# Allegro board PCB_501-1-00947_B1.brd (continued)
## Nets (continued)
VDD_SD3: C110.1 C184.1 C185.1 C186.1 C187.1 C188.1 R45.2 R46.2 R93.1 R94.1 U7.K8 U10.C6 U10.M4 U10.N4 U10.P3 U10.P5
VDD_SD_CON: C195.1 C196.1 FB42.2 J28.4 R103.1 TP83.1
VDD_SNVS_1P8_CAP: C95.1 U7.AE8
VDD_SOC_ARM: C63.1 C64.1 C65.1 C68.1 C69.1 C70.1 C71.1 C72.1 C73.1 C79.1 C80.1 C81.1 C82.1 C83.1 C84.1 C85.1 FB22.2 R718.2 TP79.1 U5.47 U7.C14 U7.C17 U7.C20 U7.D14 U7.D17 U7.D20 U7.F3 U7.F4 U7.F18 U7.F19 U7.F22 U7.F23 U7.J3 U7.J4 U7.J22 U7.J23 U7.M3 U7.M4 U7.P18 U7.R3 U7.R4 U7.R17 U7.T18 U7.U13 U7.U15 U7.U17 U7.V12 U7.V14 U7.V16 U7.V18 U50.11
VDD_SOC_ARM_L1: L3.1 U5.48
VDD_SOC_ARM_SNS: C40.1 C550.1 L3.2 R718.1 U50.12
VDD_SPK: C269.1 C270.1 FB40.2 U24.21 U24.26
VDDA_1P0_CAP: C86.1 C87.1 U7.V3
VDDA_1P8: C90.1 C91.1 C107.1 D34.2 FB2.2 U7.V5 U7.V6 U7.W5
VDDA_ADC_1P8: C130.1 C131.1 C362.1 FB3.2 U7.AB3 U7.AC3 U7.AC4
VDDA_CLKGEN_1V8: C404.1 C405.1 FB4.2 U42.16
VDDA_PHY_1P8: C66.1 C67.1 C78.1 C357.1 U7.J13 U7.Y9 U7.Y10 U7.Y11 U7.Y12
VDDA_PHY_1V8: C280.1 C283.1 C284.1 C285.1 C507.1 C508.1 FB19.1 U13.13 U13.48
VDDA_PHY_2V5: C286.1 C287.1 C288.1 C289.1 C290.1 C291.1 FB20.1 U13.3 U13.9
VDDD_1P0_CAP: C74.1 C75.1 C76.1 C77.1 U7.AA9 U7.AA10 U7.AA11 U7.AA12 U7.J15 U7.J17
VDDIO_PHY_3V3: C249.1 C250.1 C292.1 C293.1 C294.1 C295.1 C296.1 C297.1 FB21.1 R129.1 R301.2 R302.2 R306.2 R663.2 R664.2 R665.2 R688.2 U13.19 U13.30 U13.41
2G4_ANT: C529.2 M1.32
32K_OSC_EN: R705.1 Y5.1
ADDR_LGHTSEN: R674.2 R683.1 U31.2
ALS_I2C_SCL: R242.1 U31.4
ALS_I2C_SDA: R247.1 U31.6
ALS_INT: R658.2 U7.J20 U31.5
AUD_3V3: C271.1 FB41.2 R366.1 U24.32
AUD_I2C_SCL: R515.1 U24.17
AUD_I2C_SDA: R520.1 U24.18
AUDIO_MCLK: R110.2 U24.11
AUDIO_RXD: R485.2 U24.16
AUDIO_RXD_R: R485.1 U7.D16
AUDIO_TXC: R486.2 U24.12
AUDIO_TXC_R: R486.1 U7.D15
AUDIO_TXD: R483.2 U24.14
AUDIO_TXD_R: R483.1 U7.D19
AUDIO_TXFS: R487.2 U24.13
AUDIO_TXFS_R: R487.1 U7.E19
BASE_PNP: Q35.2 Q35.5 Q35.6 R615.1
BAT_CTRL: Q32.3 R613.1 R614.2
BAT_IN: C569.1 J2.1 Q32.4 Q32.8(SOURCE2)
BOOT_MODE0: SW3.4 U7.P4
BOOT_MODE1: SW3.3 U7.P5
BT_CFG4: R204.2 R697.2 SW2.8
BT_CFG5: R203.2 R698.2 SW2.7
BT_CFG6: R206.2 R699.2 SW2.6
BT_CFG10: R210.2 R700.2 SW2.5
BT_CFG11: R209.2 R701.2 SW2.4
BT_CFG12: R211.2 R702.2 SW2.3
BT_CFG13: R213.2 R703.2 SW2.2
BT_CFG14: R212.2 R704.2 SW2.1
BT_DBG: M1.43 TP55.1
BT_REG_ON: M1.41 U7.J6
BUCK_FB: C531.2 R695.1 R696.2 U46.4
BUCK_FB_L: L7.1 U46.2(SW)
BUCK_PG: R692.2 U7.L25 U46.6
CAMERA_I2C_SCL: J20.7 R639.2 U45.4
CAMERA_I2C_SDA: J20.8 R638.2 U45.5
CAMERA_PWDN: J20.13 Q39.2(SOURCE) R636.1
CAN2_RX: U7.T5 U25.4
CAN2_TX: U7.T6 U25.1
CAN_STB: R224.1 R381.1 U25.8
CANH: C282.1 J19.7 P14.2 R245.2 U25.7
CANL: C281.1 J19.2 P13.2 R246.2 U25.6
CAP_2G4_ANT: C529.1 C530.2 L8.1
CAP_IND_2G4_ANT: C530.1 J10.1(SIG)
CC_RES: BH1.1(POS) C557.1 R737.1
CCM_CLK1_N: TP8.1 U7.Y1
CCM_CLK1_P: TP7.1 U7.Y2
CCM_CLK2: R641.1 TP9.1 U7.W3
CLK_32K: R706.1 Y5.3
CLKGEN_OE0_B: R155.1 U42.12
CLKGEN_OE1_B: R449.1 U42.19
CLKGEN_Q0_N: R598.1 U42.14
CLKGEN_Q0_P: R597.1 U42.13
CLKGEN_Q1_N: R633.1 U42.18
CLKGEN_Q1_P: R632.1 U42.17
CLKGEN_XIN: C402.1 U42.1 X4.1
CLKGEN_XOUT: C403.1 U42.2(XTAL_OUT) X4.2
CODEC_GPIO_INT: U7.K24 U24.15
COLL_GPIO3: Q41.3 R752.2 R763.1
COLL_PMIC_LED: D33.1(K) Q40.3
COLLECTOR_PNP: Q34.3 Q35.3 R616.2
CSENS1_I2C_SCL: R723.1 U50.6
CSENS1_I2C_SDA: R724.1 U50.7
CSENS1_PV: R727.1 U7.L23 U50.10
CSENS2_A0: R732.1 U52.5
CSENS2_I2C_SCL: R726.1 U52.6
CSENS2_I2C_SDA: R725.1 U52.7
CSENS2_PV: R731.1 U7.L24 U52.10
CSI_AGND: J20.2 J20.4 R269.1
CSI_I2C_SCL: R516.1 U45.1
CSI_I2C_SDA: R521.1 U45.8
CSI_PIN30: J20.30 R622.1
CSI_PWDN: Q39.3 R637.1 U7.G25
CSI_RESET: C456.1 J20.9 R630.1
CSI_VDD_1V8: C446.1 C447.1 FB36.1 J20.28 R622.2 R630.2
CSI_XCLK: J20.25 Y4.3
CSI_XCLK_OE: R623.2 Y4.1
D_USB_DN: J11.2 P19.2 R160.2
D_USB_DP: J11.3 P18.2 R158.2
DBG_DA: R165.1 U18.2
DBG_RXLED1: D8.2 R161.1
DBG_RXLED2: D10.2 R166.1
DBG_TXLED1: D9.2 R162.1
DBG_TXLED2: D11.2 R167.1
DBG_XTIN: C243.2 R164.1 U18.43 X5.1
DBG_XTOUT: C244.2 R164.2 U18.44(XTOUT) X5.3
DC34_SEL: R37.2 U5.17
DC_SW: R12.1 SW1.1
DC_SW_CTL: C394.2 D20.1(K) Q2.3 R12.2 R539.1
DDR_SDCLK0_N: R618.1 U7.AD25
DDR_SDCLK0_P: R617.1 U7.AD24
DDR_VREF: C141.1 C535.1 U7.AC13 U8.H1 U8.M8 U9.H1 U9.M8 U51.6
DEBUG_5V0: C226.1 C227.1 C228.1 C239.1 C361.1 FB10.2 R157.1 R161.2 R162.2 R165.2 R166.2 R167.2 R294.2 U18.3 U18.4 U18.14 U18.31 U18.42
DEBUG_5V0_USB: FB10.1 J11.1(VBUS) P17.2
DRAM0_ZQ: R83.2 U8.L8(ZQ)
DRAM0_ZQ1: R81.1 U8.L9
DRAM1_ZQ: R84.2 U9.L8(ZQ)
DRAM1_ZQ1: R82.2 U9.L9
DRAM_ADDR0: U7.AB19 U8.N3 U9.N3
DRAM_ADDR1: U7.AB16 U8.P7 U9.P7
DRAM_ADDR2: U7.AC18 U8.P3 U9.P3
DRAM_ADDR3: U7.AC20 U8.N2 U9.N2
DRAM_ADDR4: U7.AB21 U8.P8 U9.P8
DRAM_ADDR5: U7.Y23 U8.P2 U9.P2
DRAM_ADDR6: U7.V22 U8.R8 U9.R8
DRAM_ADDR7: U7.Y22 U8.R2 U9.R2
DRAM_ADDR8: U7.W22 U8.T8 U9.T8
DRAM_ADDR9: U7.V23 U8.R3 U9.R3
DRAM_ADDR10: U7.T23 U8.L7 U9.L7
DRAM_ADDR11: U7.U22 U8.R7 U9.R7
DRAM_ADDR12: U7.T22 U8.N7 U9.N7
DRAM_ADDR13: U7.P23 U8.T3 U9.T3
DRAM_ADDR14: U7.AB18 U8.T7 U9.T7
DRAM_ADDR15: U7.AB20 U8.M7 U9.M7
DRAM_CAS_B: U7.AC14 U8.K3 U9.K3
DRAM_CS0_B: U7.AB23 U8.L2 U9.L2
DRAM_CS1_B: U7.AA22 U8.L1 U9.L1
DRAM_DATA0: U7.AD22 U8.D7
DRAM_DATA1: U7.AD23 U8.C8
DRAM_DATA2: U7.AE20 U8.C3
DRAM_DATA3: U7.AE23 U8.B8
DRAM_DATA4: U7.AE22 U8.A7
DRAM_DATA5: U7.AD19 U8.A3
DRAM_DATA6: TP15.1 TP16.1 U7.AD18 U8.A2
DRAM_DATA7: U7.AE19 U8.C2
DRAM_DATA8: U7.AE14 U8.E3
DRAM_DATA9: U7.AE18 U8.H8
DRAM_DATA10: U7.AE17 U8.F8
DRAM_DATA11: U7.AD16 U8.H7
DRAM_DATA12: U7.AE16 U8.F7
DRAM_DATA13: U7.AD14 U8.H3
DRAM_DATA14: U7.AD13 U8.G2
DRAM_DATA15: U7.AE13 U8.F2
DRAM_DATA16: U7.AA25 U9.D7
DRAM_DATA17: U7.W24 U9.C8
DRAM_DATA18: TP17.1 TP18.1 U7.V25 U9.B8
DRAM_DATA19: U7.W25 U9.A7
DRAM_DATA20: U7.AC25 U9.A2
DRAM_DATA21: U7.AB25 U9.C3
DRAM_DATA22: U7.AB24 U9.A3
DRAM_DATA23: U7.AC24 U9.C2
DRAM_DATA24: U7.R25 U9.E3
DRAM_DATA25: U7.N24 U9.H8
DRAM_DATA26: U7.P25 U9.H7
DRAM_DATA27: U7.N25 U9.F8
DRAM_DATA28: U7.U25 U9.G2
DRAM_DATA29: U7.R24 U9.F7
DRAM_DATA30: U7.U24 U9.H3
DRAM_DATA31: U7.V24 U9.F2
DRAM_DQM0: U7.AD20 U8.D3
DRAM_DQM1: U7.AD17 U8.E7
DRAM_DQM2: U7.AA24 U9.D3
DRAM_DQM3: U7.P24 U9.E7
DRAM_ODT0: U7.AC16 U8.K1 U9.K1
DRAM_ODT1: U7.AA14 U8.J1 U9.J1
DRAM_RAS_B: U7.AB15 U8.J3 U9.J3
DRAM_RESET: R116.1 U7.AC22 U8.T2 U9.T2
DRAM_SDBA0: U7.R22 U8.M2 U9.M2
DRAM_SDBA1: U7.P22 U8.N8 U9.N8
DRAM_SDBA2: U7.N23 U8.M3 U9.M3
DRAM_SDCKE0: R118.1 U7.AB17 U8.K9 U9.K9
DRAM_SDCKE1: R117.1 U7.AB22 U8.J9 U9.J9
DRAM_SDCLK0_N: R90.2 R91.2 R618.2 TP23.1 TP24.1 U8.K7 U9.K7
DRAM_SDCLK0_P: R90.1 R91.1 R617.2 TP21.1 TP22.1 U8.J7 U9.J7
DRAM_SDQS0_N: TP41.1 TP42.1 U7.AD21 U8.B7
DRAM_SDQS0_P: TP40.1 TP43.1 U7.AE21 U8.C7
DRAM_SDQS1_N: U7.AE15 U8.G3
DRAM_SDQS1_P: U7.AD15 U8.F3
DRAM_SDQS2_N: TP44.1 TP46.1 U7.Y25 U9.B7
DRAM_SDQS2_P: TP45.1 TP47.1 U7.Y24 U9.C7
DRAM_SDQS3_N: U7.T25 U9.G3
DRAM_SDQS3_P: U7.T24 U9.F3
DRAM_SDWE_B: U7.AB14 U8.L3 U9.L3
DRAM_ZQ: R86.2 U7.AB13
EEPROM_I2C1_SCL: R233.1 U41.6
EEPROM_I2C1_SDA: R237.1 U41.5
EMI_GPIO3: Q41.2(EMITTER) R764.2
ENET_INT_B: R680.2 R688.1 U7.M1
ENET_MDC: R95.1 U13.16
ENET_MDIO: R129.2 U7.R5 U13.17
ENET_RST_B: R131.2 U7.R2 U13.43
ESPI3_MISO: R358.2 U7.D9 U23.12
ESPI3_MOSI: R357.2 U7.D8 U23.14
ESPI3_SCLK: R356.2 U7.E9 U23.16
FB_HPOUTL: D23.2(K2) FB11.2 J15.2 R367.2
FB_HPOUTR: D24.2(K2) FB12.2 J15.3
FB_VDD_SD: FB42.1 Q6.3 R102.2
FT_RSTOUT_B: R159.2 U18.5
FT_RX1: U17.3 U18.23
FT_RX2: U18.39 U19.3
FT_TX1: U17.2 U18.24
FT_TX2: U18.40 U19.2
FUSE_FSOURCE: C93.1 R30.1 U7.V8
GPANAIO: TP6.1 U7.V4
GPIO1: R762.1 U5.11
GPIO3: R752.1 U5.26
GPIO_EPDC_D4: C366.1 TP10.1 U7.N22
GPIO_SD3_CLK: R444.2 U7.C1
GPIO_SD3_CMD: R445.2 U7.E1
GPIO_SD3_DATA0: R436.2 U7.B2
GPIO_SD3_DATA1: R437.2 U7.A2
GPIO_SD3_DATA2: R439.2 U7.G2
GPIO_SD3_DATA3: R438.2 U7.F1
GPIO_SD3_DATA4: R440.2 U7.F2
GPIO_SD3_DATA5: R441.2 U7.E2
GPIO_SD3_DATA6: R443.2 U7.C2
GPIO_SD3_DATA7: R442.2 U7.B1
GPIO_SD3_RESET_B: R446.2 U7.G1
GPIO_SD3_STROBE: R447.2 U7.J1
GWDOG_RST_B: C382.1 U7.N1
HP_DETEC: J15.4(TIP_SWITCH) R366.2 U24.2
HP_L: C274.1 U24.31
HP_R: C275.1 U24.29
HPOUTL: C274.2(CATHODE) C369.1 FB11.1
HPOUTR: C275.2(CATHODE) C370.1 FB12.1
HSIC_DATA: J4.1(SIG) U7.A12
HSIC_STROBE: J3.1(SIG) U7.B12
I2C1_SCL: R231.1 R232.1 R233.2 R234.1 U7.J2
I2C1_SDA: R235.1 R236.1 R237.2 R238.2 U7.K1
I2C2_SCL: R61.1 R242.2 R506.2 U7.K2
I2C2_SDA: R62.1 R247.2 R504.2 U7.K3
I2C3_SCL: R63.1 R508.2 R723.2 R726.2 U7.K5
I2C3_SDA: R64.1 R509.2 R724.2 R725.2 U7.K6
I2C4_SCL: R33.1 R515.2 R516.2 R595.2 U7.C12
I2C4_SDA: R34.1 R520.2 R521.2 R596.2 U7.D12
INT_LDO: C542.1 U5.35
JT_PWR: C572.1 H2.1 R171.1
JTAG_GND1: H2.7 R567.1
JTAG_GND2: H2.9 R568.1
JTAG_MOD: R174.2 R387.1 U7.U1
JTAG_TCK: H2.4 U7.U5
JTAG_TDI: H2.8 R169.1 U7.U3
JTAG_TDO: H2.6 U7.U6
JTAG_TMS: H2.2 R170.1 U7.U4
JTAG_TRST_B: R172.1 U7.U2
LCD1_CLK: J14.32 R109.1
LCD1_DATA0: J14.1 U7.D21
LCD1_DATA1: J14.2 U7.A22
LCD1_DATA2: J14.3 U7.B22
LCD1_DATA3: J14.4 U7.A23
LCD1_DATA4: J14.5 R204.1 U7.C22
LCD1_DATA5: J14.6 R203.1 U7.B23
LCD1_DATA6: J14.7 R206.1 U7.A24
LCD1_DATA7: J14.8 U7.F20
LCD1_DATA8: J14.10 U7.E21
LCD1_DATA9: J14.11 U7.C23
LCD1_DATA10: J14.12 R210.1 U7.B24
LCD1_DATA11: J14.13 R209.1 U7.G20
LCD1_DATA12: J14.14 R211.1 U7.F21
LCD1_DATA13: J14.15 R213.1 U7.E22
LCD1_DATA14: J14.16 R212.1 U7.D23
LCD1_DATA15: J14.17 U7.C24
LCD1_DATA16: J14.19 U7.B25
LCD1_DATA17: J14.20 U7.G21
LCD1_DATA18: J14.21 U7.E23
LCD1_DATA19: J14.22 U7.D24
LCD1_DATA20: J14.23 U7.C25
LCD1_DATA21: J14.24 U7.E24
LCD1_DATA22: J14.25 U7.D25
LCD1_DATA23: J14.26 U7.G23
LCD1_ENABLE: J14.28 U7.F25
LCD1_HSYNC: J14.29 U7.E25
LCD1_PWM: J14.50 R758.1 U7.N2
LCD1_RESET: J14.49 U7.C21
LCD1_TP_REF: C266.2 U23.9
LCD1_VSYNC: J14.30 U7.F24
LCD_I2C_SCL: J14.42 R508.1
LCD_I2C_SDA: J14.43 R509.1
LCD_PWR_EN: Q38.1 R734.2 U7.G24
LD_WLAN_B: D6.1(K) R146.1
LD_WPAN_B: D7.1(K) R147.1
LD_WWAN_B: D5.2(K) R145.1
LED_BOOT_COMPL: DA1.3 U7.H23
LED_BOOT_PROC: DA1.4(RK) U7.H22
LED_WLAN_B: J8.44 R146.2
LED_WPAN_B: J8.46 R147.2
LED_WWAN_B: J8.42 R145.2
LIN1: C260.1 U24.4
LIN2: C318.1 U24.3
LVLTXR_OE: R640.1 U45.6
MIC_N: MK1.2 R678.2 R679.1 R684.2
MIC_P: C318.2 MK1.1(POS) R182.2
MICBIAS: C272.1 R182.1 U24.1
MIPI_CSI_CLK_N: J20.20 U7.A15
MIPI_CSI_CLK_P: J20.19 U7.B15
MIPI_CSI_D0_N: J20.23 U7.A16
MIPI_CSI_D0_P: J20.22 U7.B16
MIPI_CSI_D1_N: J20.17 U7.A14
MIPI_CSI_D1_P: J20.16 U7.B14
MIPI_VREG_0P4V: C92.1 U7.H18
MX7_ONOFF: C367.1 R249.1 SW6.3 SW6.4 U7.AC8
MX7_RST_B: C368.1 D21.1(K) R347.1
NVCC_DRAM_CKE: C140.1 R85.1 U7.Y20
OTG1_CHD_B: TP48.1 U7.C7
OTG1_REXT: R66.2 U7.A7
OTG2_REXT: R70.2 U7.A11
OTG_VBUS: C298.1 FB18.2 Q24.3 R570.2 R571.1
OTG_VBUS_CTRL: Q24.1 Q25.3 R570.1
OUT3: C276.1 U24.30
OVRPRTC: Q5.1 R6.1 R8.2
OVRPRTC_LED: D2.1(K) Q5.3
OVRPRTC_LED_PWR: D2.2 R4.2
PCIE_CLK_GEN_SCL: R595.1 U42.8
PCIE_CLK_GEN_SDA: R596.1 U42.9
PCIE_CLKGEN_SS_SEL: R604.1 U42.23
PCIE_CTXM: C207.2 J8.31
PCIE_CTXP: C208.2 J8.33
PCIE_DIS_B: J8.20(W_DISABLE#) U7.T2
PCIE_REFCLK_N: R607.2 R608.1 R633.2 U7.AE10
PCIE_REFCLK_P: R605.2 R606.1 R632.2 U7.AD10
PCIE_REFCLKOUT_N: R598.2 R645.1 U7.AC10
PCIE_REFCLKOUT_N0: J8.11 R634.2 R645.2
PCIE_REFCLKOUT_P: R597.2 R644.1 U7.AB10
PCIE_REFCLKOUT_P0: J8.13 R635.2 R644.2
PCIE_REXT: R80.2 U7.AA13
PCIE_RST_B: J8.22 U7.T3
PCIE_RX_N: R96.1 U7.AE11
PCIE_RX_P: R97.1 U7.AD11
PCIE_RXN_R: J8.23 R96.2
PCIE_RXP_R: J8.25 R97.2
PCIE_SMB_CLK: J8.30 R506.1
PCIE_SMB_DATA: J8.32 R504.1
PCIE_TX_N: C207.1 U7.AC11
PCIE_TX_P: C208.1 U7.AB11
PCIE_UIM_CLK: J7.C3 J8.12
PCIE_UIM_DATA: J7.C7 J8.10
PCIE_UIM_PWR: C571.1 J7.C1 J8.8
PCIE_UIM_RST: J7.C2 J8.14
PCIE_UIM_VPP: J7.C6(VPP) J8.16
PCIE_USB_DM: FL3.4 J8.36
PCIE_USB_DP: FL3.1 J8.38
PHY_CLKOUT: TP62.1 U13.18
PHY_CT: C576.1 J27.1
PHY_GPIO0: R664.1 R666.2 U13.39
PHY_GPIO1: R665.1 R667.2 U13.40
PHY_INT_B: R680.1 U13.44
PHY_JTAG: R741.1 U13.20 U13.22 U13.23
PHY_LED0: D14.2 R663.1 R668.2 U13.47
PHY_LED1: J27.13 R301.1 R307.2 U13.46
PHY_LED2: J27.12 R302.1 R308.2 U13.45
PHY_MDI_A_M: J27.3 U13.2 U53.2 U53.9
PHY_MDI_A_P: J27.2 U13.1 U53.1 U53.10(NC4)
PHY_MDI_B_M: J27.5 U13.5 U53.5 U53.6
PHY_MDI_B_P: J27.4 U13.4 U53.4 U53.7
PHY_MDI_C_M: J27.7 U13.8 U54.2 U54.9
PHY_MDI_C_P: J27.6 U13.7 U54.1 U54.10(NC4)
PHY_MDI_D_M: J27.9 U13.11 U54.5 U54.6
PHY_MDI_D_P: J27.8 U13.10 U54.4 U54.7
PHY_RBIAS: R669.1 U13.12
PHY_XI: C305.1 U13.15 X3.1
PHY_XO: C304.1 R130.2 X3.3
PMIC_AC_DET: C556.2 Q37.3 R448.1 SW9.2 U5.9
PMIC_ENABLE: R350.1 R687.1 R735.2 U5.46 U7.AB8
PMIC_ENABLE_ACDET: Q37.1 R736.1
PMIC_GPIO1: R749.1 R762.2 U46.5 U47.3 U49.3 U51.7 U55.A3
PMIC_I2C1_SCL: R232.2 U5.3
PMIC_I2C1_SDA: R236.2 U5.2
PMIC_INT_B: R47.2 R685.2 U7.N5
PMIC_PB_B: R689.1 SW4.3 SW4.4 U5.44
PMIC_PFI: R31.1 R40.2 U5.16
PMIC_PFO_B: R686.2 U5.10 U7.N3
PMIC_PWR: C50.1 C51.1 C52.1 C53.1 C438.1 C439.1 C512.1 C513.1 C568.1 Q32.1 Q32.2 Q32.5 Q32.6 Q32.7 Q34.1 Q34.2 Q34.5 Q34.6 Q34.7 Q35.4(EMITTER2) R31.2 R448.2 R689.2 R738.2 U5.1 U5.6 U5.12 U5.32 U5.36 U5.37 U5.43 U46.7 U46.8
PMIC_SD_VSEL: R742.2 U7.R1 U55.B3
PMIC_STBY: Q41.1 R753.1
PMIC_STBY_R: R753.2 U7.AC7
PMIC_WAKE_B: R751.2 U5.40(WAKEUP#) U7.J25
POR_B: D26.2 Q40.1 R690.2 R750.1 U7.R6
PSU_5V0: C1.1 C2.1 C3.1 P12.2 Q2.1 Q2.2 Q2.5 Q2.6 Q2.7 Q34.4 Q34.8(SOURCE2) Q35.1 R1.1 R613.2 TP1.1
PWR_LED: D1.2 R1.2
PWR_OV_BASE: Q17.1 R537.1
PWR_OV_CTL: D17.1(K) R537.2 R538.1
PWR_OVP_LED: D20.2 Q17.3 R6.2
QSPIA_DA0: TP11.1 U7.P20 U11.5
QSPIA_DA1: U7.P21 U11.2
QSPIA_DA2: U7.N20 U11.3(W#/DQ2)
QSPIA_DA3: U7.N21 U11.7
QSPIA_SCLK: U7.M20 U11.6
QSPIA_SS0_B: R92.2 U7.M21 U11.1
RES_BUCK_FB: R694.1 R695.2
RES_CAN_STB: R381.2 U7.L20
RES_INT_B: R47.1 U5.45
RES_LCD1_PWM: D35.2 R758.2
RES_LED_BOOT_COMP: DA1.1 R739.1
RES_LED_BOOT_PROC: DA1.2 R740.1
RES_PHY_LED0: D14.1(K) R293.1
RES_PHY_LED1: J27.14 R303.1
RES_PHY_LED2: J27.11 R297.1
RES_PMIC_LED: D33.2 R738.1
RES_POR_B: R690.1 U5.8
RES_SD1_RST: Q8.1 R108.2
RES_TP_BUSY: R380.1 U7.K25
RES_VDD_SD_CON: Q7.3 R103.2
RGMII1_RX_CTL: R283.2 U7.E15
RGMII1_RXC: R282.2 U7.F15
RGMII1_RXD0: R278.2 U7.E14
RGMII1_RXD1: R279.2 U7.F14
RGMII1_RXD2: R280.2 U7.D13
RGMII1_RXD3: R281.2 U7.E13
RGMII1_TX_CTL: R532.1 U13.37
RGMII1_TXC: R527.1 U13.29
RGMII1_TXD0: R528.1 U13.28
RGMII1_TXD1: R526.1 U13.27
RGMII1_TXD2: R525.1 U13.26
RGMII1_TXD3: R530.1 U13.25
RGMII_TCTRL: R532.2 U7.E16
RGMII_TD0: R528.2 U7.F17
RGMII_TD1: R526.2 U7.E17
RGMII_TD2: R525.2 U7.E18
RGMII_TD3: R530.2 U7.D18
RGMII_TXC: R527.2 U7.F16
RTC_XO: C103.1 R285.2 X1.2
RTC_XTALI: C102.1 R36.1 U7.AE6 X1.1
RTC_XTALO: R36.2 R285.1 U7.AD6
RX_CLK: R282.1 U13.32
RX_CTRL: R283.1 R300.2 R306.1 U13.38
RX_D0: R278.1 U13.33
RX_D1: R279.1 U13.34
RX_D2: R280.1 U13.35
RX_D3: R281.1 U13.36
RX_LED1: D8.1(K) U18.12
RX_LED2: D10.1(K) U18.28
SAI1_MCLK: R110.1 U7.E10
SCHO_MR_B: C382.2 D22.1(K) R349.1
SCHO_PWR_DISCH: D4.1(K) Q8.3 R107.2
SD1_CD_B: J28.10 P26.2 R101.2 U7.C6
SD1_CLK: P24.2 R49.1 R106.1
SD1_CLK_R: C197.1 J28.5 R106.2
SD1_CMD: J28.2 P25.2 R39.1 R99.2
SD1_DATA0: J28.7 P20.2 R41.1
SD1_DATA1: J28.8 P21.2 R42.1
SD1_DATA2: J28.9 P22.2 R43.1
SD1_DATA3: J28.1 P23.2 R44.1
SD1_RESET_B: R108.1 R491.1 U7.B4
SD1_WP: J28.11(WRITE_PROTECT_SWITCH) P27.2 R100.2 U7.C4
SD2_CLK: R176.1 R286.1
SD2_CMD: R177.1 R287.1 R711.1
SD2_DATA0: R178.1 R288.1 R707.1
SD2_DATA1: R179.1 R289.1 R708.1
SD2_DATA2: R180.1 R290.1 R709.1
SD2_DATA3: R181.1 R291.1 R710.1
SD3_CLK: R125.1 R444.1
SD3_CLK_R: R125.2 U10.M6
SD3_CMD: R94.2 R445.1 U10.M5
SD3_DATA0: R436.1 U10.A3
SD3_DATA1: R437.1 U10.A4
SD3_DATA2: R439.1 U10.A5
SD3_DATA3: R438.1 U10.B2
SD3_DATA4: R440.1 U10.B3
SD3_DATA5: R441.1 U10.B4
SD3_DATA6: R443.1 U10.B5
SD3_DATA7: R442.1 U10.B6
SD3_RESET_B: R93.2 R446.1 U10.K5
SD3_STROBE: R124.1 R447.1
SD3_STROBE_R: R124.2 R691.2 U10.H5
SD_PWR_CTRL: C194.2 Q6.1 R105.2 R107.1
SD_PWR_DISCH: D4.2 Q7.1 R104.2
SOC_OTG2_DN: R559.1 R566.1 U7.A10
SOC_OTG2_DP: R558.1 R565.1 U7.B10
SOC_SD1_CLK: R49.2 U7.B5
SOC_SD1_CMD: R39.2 U7.C5
SOC_SD1_DATA0: R41.2 U7.A5
SOC_SD1_DATA1: R42.2 U7.D6
SOC_SD1_DATA2: R43.2 U7.A4
SOC_SD1_DATA3: R44.2 U7.D5
SOC_SD2_CLK: R286.2 U7.E3
SOC_SD2_CMD: R287.2 U7.F6
SOC_SD2_DATA0: R288.2 U7.E4
SOC_SD2_DATA1: R289.2 U7.E5
SOC_SD2_DATA2: R290.2 U7.F5
SOC_SD2_DATA3: R291.2 U7.E6
SPI3_MISO: J14.40 R358.1
SPI3_MOSI: J14.39 R357.1
SPI3_SCLK: J14.38 R356.1
SPI_SS_B: H4.3 J14.41
SPKLN: D28.2(K2) FB17.2 H3.2
SPKLP: D27.2(K2) FB14.2 H3.1
SPKOUTLN: FB17.1 U24.23
SPKOUTLP: FB14.1 U24.25
SPKOUTRN: FB16.1 U24.19
SPKOUTRP: FB13.1 U24.22
SPKRN: D30.2(K2) FB16.2 H3.4
SPKRP: D29.2(K2) FB13.2 H3.3
ST_CANH: C506.1 R245.1 R246.1
ST_CLK_32K: M1.36 R706.2
ST_ENET_MDC: R95.2 U7.T1
ST_JTAG_TRS: D26.1(K) H2.10 R168.1 R172.2
ST_LCD_CLK: R109.2 U7.E20
ST_MIC_N: C260.2 R660.2 R684.1
ST_PHY_XO: R130.1 U13.14(XO)
SUPER_CT: C393.1 U37.4
SUPER_MR_B: D21.2 D22.2 R127.1 U37.3
SUPER_RST_B: R350.2 R736.2 U37.1
SUPER_SENSE: C401.1 D16.2 R348.1 U37.5
SW_BT_MODE0: R295.1 SW3.1
SW_BT_MODE1: R296.1 SW3.2
SW_MX7_RST_B: R347.2 SW8.3 SW8.4
SW_USR_BT0: C578.1 R309.2 SW5.3 SW5.4
SW_USR_BT1: C579.1 R310.2 SW7.3 SW7.4
TEMP_SENSOR_REXT: R75.2 U7.AE4
TEST_MODE: R35.1 U7.P6
TMPSEN_RESERV: R76.2 U7.AD4
TOUCH_X1: J14.34 R590.2
TOUCH_X1_C: C420.2 R590.1 U23.2
TOUCH_X2: J14.35 R592.2
TOUCH_X2_C: C422.2 R592.1 U23.4
TOUCH_Y1: J14.36 R591.2
TOUCH_Y1_C: C421.2 R591.1 U23.3
TOUCH_Y2: J14.37 R593.2
TOUCH_Y2_C: C423.2 R593.1 U23.5(Y-)
TP_BUSY: R380.2 U23.13
TP_ESPI3_SS2_B: U7.D3 U33.2
TP_ESPI_SS_B: H4.2 R656.2 U33.4(Y)
TP_INT_B: U7.K23 U23.11
TP_OUT3: C276.2 TP29.1
TP_SPI_SS_B: H4.1 U23.15
TPS51200_PG: R715.2 TP76.1 U51.9
TPS51200_REFIN: C534.1 R716.1 R717.2 U51.1
TX_LED1: D9.1(K) U18.11
TX_LED2: D11.1(K) U18.27
UART1_RXD: U7.L3 U17.6
UART1_TXD: U7.L4 U17.5
UART2_RXD: U7.L5 U19.6
UART2_TXD: U7.L6 U19.5
UART5_CTS: H5.3 U7.D11
UART5_RTS: H5.2 U7.E11
UART5_RX: H5.4 U7.L1
UART5_TX: H5.5 U7.L2
UART6_CTS_B: R755.2 R756.2 TP53.1 U7.H5
UART6_RTS_B: R754.2 R757.2 TP52.1 U7.H4
UART6_RXD: M1.52 TP51.1 U7.H3
UART6_TXD: M1.53 TP50.1 U7.G5
USB2ANY_I2C1_SCL: H1.1 R234.2
USB2ANY_I2C1_SDA: H1.2 R238.1
USB_DN: R160.1 U18.8
USB_DP: R158.1 R159.1 U18.7
USB_HOST_N: FL2.3 J26.2 P11.2
USB_HOST_P: FL2.2 J26.3 P8.2
USB_HOST_VBUS: C299.1 C300.2 J26.1(VBUS) P10.2 R69.2 R569.2 U30.5(OUTB)
USB_OTG1_DN: FL1.3 U7.A8
USB_OTG1_DP: FL1.2 U7.B8
USB_OTG1_ID: J25.4 P5.2 U7.B7
USB_OTG1_OC: R257.1 U7.N6 U30.2
USB_OTG1_PWR: R126.2 R253.1 U7.P1 U30.1
USB_OTG2_DN: FL2.4 R566.2
USB_OTG2_DP: FL2.1 R565.2
USB_OTG2_ID: R68.1 U7.B11
USB_OTG2_OC: R255.1 U7.P2 U30.3
USB_OTG2_PWR: R252.1 R254.2 U7.P3 U30.4
USB_OTG_N: FL1.4 J25.2 P6.2
USB_OTG_P: FL1.1 J25.3 P7.2
USB_OTG_PWR: FB18.1 J25.1(VBUS) P4.2
USB_OTG_SHIELD: C252.1 J25.S1 J25.S2 R251.1
USB_OTG_VBUS: Q24.2(SOURCE) R65.2 R569.1 R571.2 U30.8
USB_PCIE_DN: FL3.3 R559.2
USB_PCIE_DP: FL3.2 R558.2
USB_SUSPEND1_B: U17.1 U17.7 U18.13
USB_SUSPEND2_B: U18.29 U19.1 U19.7
USR_BT0: R309.1 U7.G3
USR_BT1: R310.1 U7.C3
VMIDC: C273.1 U24.27(VMID)
VSNVS: C94.1 C573.1 D16.1(K) D34.1(K) R127.2 R249.2 R348.2 R687.2 R737.2 R763.2 U7.AD8 U37.6(VDD)
WL_DBG: M1.42 TP54.1
WL_IRQ: M1.14 R682.1 U7.H6
WL_REG_ON: M1.40 U7.G6
WL_RX: M1.26 TP56.1
WL_SDIO_CLK: C224.1 M1.8 R176.2
WL_SDIO_CMD: C223.1 M1.6 R177.2
WL_SDIO_D0: C222.1 M1.10 R178.2
WL_SDIO_D1: C221.1 M1.11 R179.2
WL_SDIO_D2: C220.1 M1.12 R180.2
WL_SDIO_D3: C219.1 M1.13 R181.2
WL_TX: M1.27 TP57.1
WL_UART6_CTS: M1.51 R755.1 R757.1
WL_UART6_RTS: M1.50 R754.1 R756.1
XTALI: C105.1 R38.2 U7.V1 X2.1
XTALO: R38.1 R284.1 U7.V2
XTC_XO: C106.1 R284.2 X2.3

Pads without a net: FD1 1; FD2 1; FD3 1; FD4 1; FD5 1; FD6 1; FD7 1; FD8 1; FD9 1; FD10 1; FD11 1; FD12 1; FD13 1; FD14 1; H1 3 4 5 7 8 9 10; J7 C4 C8; J8 1 3 5 7 17 19 45 47 49 51; J11 4; J14 M1 M2; J19 1 3 4 8 9; J20 1 10 27; M1 2 3 4 5 18 21 22 25 56 57 58 60 62; MECH1 1; MECH2 1; MECH3 1; MECH4 1; SW1 3 S1 S2; U5 18 19 28 29 34; U7 A18 A19 A20 AA3 AA4 AA5 AA7 AB6 B18 B19 B20 C11 E8 E12 H20 H21 H24 H25 J5 J21 J24 K20 K21 L21 L22 M2 M5 M6 M22 M23 Y3 Y4 Y5 Y7 Y8; U10 A1 A2 A7 A8 A9 A10 A11 A12 A13 A14 B1 B7 B8 B9 B10 B11 B12 B13 B14 C1 C3 C5 C7 C8 C9 C10 C11 C12 C13 C14 D1 D2 D3 D4 D12 D13 D14 E1 E2 E3 E5 E8 E9 E10 E12 E13 E14 F1 F2 F3 F10 F12 F13 F14 G1 G2 G3 G10 G12 G13 G14 H1 H2 H3 H12 H13 H14 J1 J2 J3 J12 J13 J14 K1 K2 K3 K6 K7 K10 K12 K13 K14 L1 L2 L3 L12 L13 L14 M1 M2 M3 M7 M8 M9 M10 M11 M12 M13 M14 N1 N3 N6 N7 N8 N9 N10 N11 N12 N13 N14 P1 P2 P7 P8 P9 P10 P11 P12 P13 P14; U13 21; U18 1 10 15 16 17 19 20 21 22 26 30 32 33 35 36 37 38 41 48; U23 8; U24 5 6 7; U33 1; U42 4 22; U50 8 9 13; U52 8 9 13

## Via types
v1: diameter 0.457, hole 0.254, TOP to BOTTOM, 1669 vias
v2: diameter 0.406, hole 0.203, TOP to BOTTOM, 605 vias
v3: diameter 0.61, hole 0.305, TOP to BOTTOM, 350 vias

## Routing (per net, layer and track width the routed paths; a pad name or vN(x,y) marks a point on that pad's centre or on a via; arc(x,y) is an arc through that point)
3V3OUT: length 1.9
  BOTTOM w0.305: U18.6 104.48,119.29 C240.1
5VIN: length 7.1
  TOP w0.381: R4.1 v1(36.03,99.57)
  BOTTOM w0.203: v1(36.03,99.57) v1(36.03,106.05)
AVCC_DBG_5V0: length 1.9
  BOTTOM w0.305: R157.2 98.8,114.63 U18.46
GND: length 1483.9
  TOP w0.076: 67.44,60.53 67.17,60.81 v1(66.87,60.81) 66.87,60.4 67.12,60.15 67.37,59.9 U10.N2
  TOP w0.081: 67.44,60.53 67.72,60.25 U10.N2
  TOP w0.127: v1(74.45,87.21) 74.44,87.22 ; 74.44,87.22 74.44,87.23 74.38,87.29 74.37,87.29 ; 74.44,87.22 74.37,87.29 ; v1(75.28,87.38) 75,87.66 72.92,87.66 72.66,87.4 U7.AE3 72.66,87.36 ; v1(76,86.12) 75.91,86.03 74.77,86.03 74.51,85.77 U7.AD1 ; v1(74.99,84.19) 74.93,84.19 74.59,83.85 73,83.85 72.13,84.71 U7.AB1 ; U7.AD3 72.67,86.83 73.14,87.29 74.37,87.29 ; v1(74.06,84.58) 73.32,84.58 U7.AC1 ; 74.87,81.31 73.55,82.63 72.94,82.63 72.7,82.39 v1(71.53,82.39) ; U7.AE2 73.19,86.83 73.25,86.77 74.98,86.77 v1(75.24,86.51) ; v1(74.9,85.37) 74.85,85.32 73.11,85.32 72.67,85.77 U7.AC2 ; U10.N5 U10.P6 ; v1(75.71,85.16) 75.3,84.75 74.89,84.75 74.26,84.12 73.24,84.12 72.13,85.24 U7.AB2
  TOP w0.152: J20.26 2.11,44.75 1.66,44.29 v1(1.19,44.29)
  TOP w0.203: U10.A6 73.57,62.92 73.67,63.02 73.97,63.02 v1(73.99,63) ; J20.18 2.11,47.95 v1(1.61,48.44) ; U5.22 15.08,90.49 v3(14.88,90.69) 14.68,90.48 U5.23 ; v1(7.09,45.41) 7.05,45.41 6.78,45.15 J20.6 ; D30.1 v1(93.95,34.91) ; J20.24 2.05,45.55 1.96,45.47 v1(1.96,45.47) ; U5.25 v1(13.5,89.86) 13.52,89.84 U5.24 ; J20.21 2.08,46.75 2,46.83 v1(1.96,46.83) ; v1(1.53,42.17) 1.53,42.82 2.26,43.55 J20.29 ; J20.14 6.68,48.35 6.88,48.55 v1(6.88,48.56) 6.69,48.75 J20.15 ; U5.20 15.88,90.44 15.67,90.64 v3(15.67,90.64) 15.48,90.45 U5.21 ; J20.11 6.68,47.15 v1(6.86,47.33) 6.86,47.35 6.66,47.55 J20.12 ; D24.1 v1(112.16,35.92) ; v1(101.52,33.35) 101.64,33.23 D27.1 ; v1(99.38,35.61) D28.1 ; v1(71.01,61.79) 70.85,61.63 70.85,61.02 U10.G5 ; D23.1 v1(112.13,38.98) ; v1(71.96,62.04) 71.96,62.04 71.96,62.73 U10.C4 ; D29.1 v1(96,33.39)
  TOP w0.229: P4.1 v1(50.02,6.1) ; v1(31.21,98.17) P12.1 v1(31.76,98.89) ; P18.1 v1(123.32,108.8) ; P13.1 v1(74.05,13.88) ; P14.1 v1(75.87,13.88) ; P5.1 55.81,5.75 ; P17.1 v1(123.92,104.98) ; P7.1 v1(54.16,5.63) ; P19.1 v1(123.32,107.1) ; P8.1 v1(46.58,16.98) ; v1(46.58,15.28) 47.08,15.28 P11.1 ; P6.1 v1(52.46,5.63)
  TOP w0.254: U8.E2 72.51,106.41 v2(72.9,106.02) ; v1(71.34,59.09) 71.15,59.09 71.15,59.09 U10.K8 ; v1(72.88,61.08) 72.85,61.11 72.47,61.11 U10.E7 ; v2(53.57,82.58) 53.57,82.58 U7.C16 ; U7.AC21 v2(62.06,96.37) ; v2(60.62,89.85) 60.66,89.81 60.67,89.81 U7.T16 ; v2(69.48,87.89) 69.48,87.89 U7.AB7 ; U10.J5 v1(70.62,59.83) ; v2(68.1,107.62) U8.G8 U8.F9 ; v2(67.5,95.97) 67.5,96.63 TP69.1 ; U24.24 98.29,36 v1(98.51,35.78) ; v1(68.85,57.34) 68.78,57.41 U10.P6 ; U7.R21 57.81,92.12 v2(57.81,92.12) ; U9.E8 v2(50.13,106.83) ; U7.N4 65.77,80.99 v2(65.77,80.99) ; v2(62.07,80.49) 62.06,80.5 ; 62.06,80.5 61.85,80.5 61.28,79.93 U7.G7 60.47,79.93 v2(60.47,79.93) ; 62.06,80.5 62.06,80.53 62.06,80.54 U7.J7 ; U7.M14 v2(59.42,86.3) ; 67.36,86.3 U7.Y6 68.95,86.3 v2(68.95,86.29) ; v2(61.77,84.75) 62.06,85.03 U7.N11 ; v2(63.12,95.32) 63.12,95.32 U7.AC19 ; U7.C19 52.51,83.65 v2(52.51,83.64) 52.51,83.64 53.04,83.64 U7.C18 ; U7.R20 58.34,91.59 v2(58.34,91.59) ; v2(56.76,83.65) 56.75,83.66 U7.G15 ; U8.G1 v2(73.72,107.6) ; U7.P12 61.81,86.3 v2(61.52,86) ; v2(68.45,86.83) 68.95,86.83 U7.AA6 ; U8.B9 66.34,104.02 v2(66.31,103.99) ; 122.39,64.91 U46.1 ; U7.T4 67.89,83.11 v2(67.89,83.11) ; v2(61,76.22) 60.99,76.22 U7.D4 ; U9.B1 v2(56.72,104.02) ; v2(71.07,86.29) 71.07,86.3 U7.AB4 ; U7.N15 60.27,87.36 v2(60.46,87.55) ; U8.G9 66.37,108.02 v2(66.37,108.02) ; U7.G19 v2(54.1,86.3) ; U9.A9 49.5,103.22 v2(49.27,102.99) ; v2(62.59,77.81) 62.59,77.81 U7.G4 ; U5.27 12.88,88.27 v1(12.55,88.59) ; U7.L7 63.45,82.05 v2(63.76,82.36) 64.18,82.78 U7.N7 ; U8.E1 73.31,106.42 v2(73.79,105.94) ; v2(56.71,105.64) 56.69,105.62 U9.D1 ; U7.F8 60.46,79.93 v2(60.47,79.93) ; U46.3 122.95,65.92 122.34,65.92 122.29,65.87 ; v1(96.18,35.68) 96.18,35.69 96.21,35.72 96.21,35.84 96.29,35.92 U24.20 ; U7.T14 61.67,88.42 v2(61.52,88.57) ; U7.R23 v2(56.75,93.19) ; U9.B3 54.55,104.02 v2(54.93,103.64) ; U8.P1 v2(72.91,114.02) ; U8.J2 v2(72.15,109.98) ; U7.K10 60.99,82.58 v2(61,82.58) ; U7.K14 v2(59.39,85.24) ; SW4.2 2.54,68.78 v1(1.44,68.78) ; U7.AB9 68.02,88.95 68.42,89.35 U7.AC9 68.95,89.48 v2(68.95,89.48) ; U7.J19 56.21,87.88 v2(56.21,88.12) ; v2(65.75,114.34) 66.48,113.62 U8.P9 ; v2(66.35,112.01) 66.35,112.02 U8.M9 ; U7.L13 v2(59.93,85.74) ; 57.03,88.42 57.44,88.83 57.48,88.83 ; U7.AA23 v2(59.93,96.37) ; U9.G8 v2(50.87,107.69) ; U8.A9 66.74,103.22 v2(66.29,102.77) ; U24.28 99.06,38.79 v1(99.87,38.79) ; v2(66.87,115.93) 66.91,115.89 U8.T9 ; U7.AB12 66.3,91.06 v2(66.3,91.06) ; U7.V20 60.5,92.1 v2(60.5,91.72) ; v2(55.76,107.64) 56.13,108.02 U9.G1 ; U7.U20 60.16,91.37 60.16,91.14 v2(60.18,91.14) ; v2(60.29,88.07) U7.P16 ; U54.8 v1(31.59,24.61) ; v1(78.83,98.04) 78.56,98.04 U42.10 ; v2(68.1,110.01) 67.71,109.62 U8.J8 ; U9.J8 v2(50.17,109.23) ; U7.AC23 v2(60.99,97.43) ; U7.T10 64.18,85.75 64.18,85.75 v2(64.18,85.74) ; v2(61,92.13) 60.99,92.13 U7.W19 U7.W20 ; v2(60.57,81.71) 60.57,81.64 59.93,81 U7.G9 ; v2(60.47,79.93) 60.47,79.4 U7.F7 ; U8.E8 67.73,106.42 v2(68.12,106.03) U8.D8 ; U9.D8 v2(50.18,105.24) ; U7.L15 v2(58.87,85.78) ; U9.M1 v2(57.04,112.02) ; v2(63.64,89.48) 63.64,89.48 U7.W13 U7.Y13 U7.Y14 63.66,90.54 v2(63.65,90.55) ; v1(72.88,58.67) 72.49,58.67 U10.H10 ; U8.T1 v2(72.91,115.62) ; v1(93.22,40.98) 93.41,40.79 U24.9 ; U7.AE5 71.92,88.73 v2(72.02,88.73) ; U7.G22 v2(52.51,87.89) ; U7.M12 61.51,85.24 v2(61.51,85.23) ; U7.C13 v2(55.69,80.46) ; U7.W4 68.95,84.18 v2(68.95,84.17) ; U7.K4 64.18,79.4 v2(64.18,79.4) ; v2(49.12,113.61) 49.75,113.61 U9.P9 ; U7.U23 v2(57.81,94.25) ; v2(58.87,91.07) 58.87,91.07 U7.T20 ; U7.R15 60.99,87.9 v2(61,87.9) ; U7.W9 66.36,87.29 v2(66.36,86.84) ; v2(49.73,115.87) 49.75,115.85 U9.T9 ; U7.D22 50.92,86.3 v2(50.92,86.3) ; U42.24 v1(82.23,97.58) ; U7.P14 61,87.36 v2(61.51,87.36) 61.51,87.36 U7.R13 ; U7.P10 63.12,85.01 63.12,84.83 63.12,84.74 v2(63.12,84.74) ; v2(73.73,105.18) 73.31,105.6 U8.D1 ; TP32.1 v1(8.35,99.95) ; U42.5 81.03,100.13 C410.2 80.61,100.42 U42.6 ; U8.B1 73.31,104.02 v2(73.74,103.58) ; v2(58.87,86.84) U7.M16 58.87,87.36 ; U7.AA15 64.18,92.07 v2(64.18,92.08) ; v2(70.54,87.89) 70.54,87.89 U7.AC6 ; 68.07,58.84 67.85,58.61 67.64,58.41 v1(67.48,58.41) ; U8.M1 v2(72.91,112.42) ; v2(58.36,90.55) 58.37,90.54 U7.R19 ; v2(57.27,83.15) 57.28,83.13 U7.F13 ; v2(62.79,86.74) 62.79,86.62 U7.R11 ; v2(49.17,107.22) 49.17,107.22 U9.F9 ; U7.L11 U7.K12 v2(59.93,83.65) ; U9.M9 v2(50.15,111.61) ; U9.P1 v2(57.04,113.62) ; U9.G9 v2(49.18,108.02) ; U42.21 80.97,95.63 81.29,95.63 81.35,95.58 ; v2(61.26,86.71) 60.99,86.44 U7.N13 ; 55.81,5.75 v1(55.85,5.71) ; U7.F11 v2(58.87,81.52) ; U7.W23 v2(58.87,95.31) ; SW4.1 v1(1.55,77.78) ; U7.W11 65.68,87.98 v1(65.68,87.71) ; v2(68.42,87.89) 68.42,87.89 U7.AA8 ; 61.52,93.19 U7.Y19 61.53,92.65 61.51,92.63 61.51,92.64 v2(61.51,92.64) ; U8.B3 v2(71.33,103.64) ; U7.G11 v2(58.35,82.05) ; U53.8 v1(25.75,24.61) ; v2(62.29,83.63) 62.06,83.86 U7.M10 ; U7.R7 65.24,84.47 65.69,84.91 v2(65.7,84.91) ; U7.K22 v2(54.1,89.48) ; U7.AC12 66.83,91.59 v2(66.83,91.59) 66.84,91.6 U7.AD12 U7.AE12 67.89,92.16 67.93,92.2 v2(68.9,93.17) ; v2(56.84,115.24) 56.81,115.22 U9.T1 ; U51.4 81.38,112.78 81.64,112.52 U51.11 ; U7.K16 v2(58.33,86.3) ; 57.81,90 U7.N19 ; U54.3 v1(31.59,22.38) ; U53.3 v1(25.75,22.38) ; U7.AB5 70.01,86.83 70.54,86.83 v2(70.54,86.82) ; v2(49.18,103.97) 49.23,104.02 U9.B9 ; U7.AC15 v2(65.24,93.19) ; U7.U7 v2(66.3,84.73) ; U7.C15 v2(54.1,82.05) ; v2(58.32,83.11) U7.G13 ; U9.E1 56.15,106.45 v2(55.76,106.83) 55.35,106.42 U9.E2 ; U7.G17 56.1,85.24 v2(56.18,85.32) ; U50.5 v1(17.12,64.65) ; U9.J2 v2(54.95,110.02)
  TOP w0.305: U7.T12 63.12,87.36 U7.T12 ; U7.T12 63.12,87.36 v2(63.67,86.8) 63.67,86.85 U7.U11 64.18,87.36 ; U7.T12 62.79,87.03 v2(62.79,86.74) ; v1(77.59,81.31) 77.92,81.31 80.23,78.99 v1(80.23,78.87) 80.23,78.57 79.52,77.86 79.52,77.86 78.42,76.76 78.42,76.76 78.24,76.58 v1(78.12,76.58) 78.12,76.42 76.81,75.11 76.77,75.11 75.96,74.3 v1(75.66,74.3) 75.46,74.3 74.01,75.74 v1(73.88,75.74) ; v1(77.59,81.31) 74.87,81.31 ; v1(77.59,81.31) 77.59,81.86 R641.2 ; U7.D7 59.4,77.8 v2(59.4,77.8) ; v1(49.78,83.64) 49.85,83.64 U7.A21 U7.B21 ; U45.2 26.79,57.08 v1(26.7,57.17) ; U42.15 78.51,96.9 v1(78.83,96.9) ; U7.AD9 68.95,90.17 69.32,90.54 U7.AE9 69.48,90.72 69.87,91.11 v2(70.22,91.11) ; U7.B17 U7.A17 52.51,81.75 52.28,81.52 v1(52.05,81.52) ; v1(47.81,85.96) 47.93,85.96 U7.A25 ; v2(65.21,76.78) U7.H1 U7.H2 ; v2(55.69,80.46) 55.69,80.46 U7.B13 U7.A13 54.15,79.46 v1(54.06,79.46) ; U7.AC17 v2(64.18,94.25) ; U7.N19 57.81,90 v2(57.81,90) ; U7.AE24 v2(61.53,99.02) U7.AE25 ; U7.D2 U7.D1 62.82,74.93 62.82,74.89 v1(63.27,74.43) ; C407.2 75.55,100.54 v1(75.23,100.86) ; U7.C9 57.81,79.4 ; 57.81,79.4 U7.D10 ; 57.81,79.4 v2(57.81,79.4) 57.81,79.4 ; v2(57.49,88.85) 57.06,88.42 U7.L19 ; v1(56.1,77.06) 56.48,77.06 56.75,77.33 U7.A9 U7.B9 ; U7.AA2 U7.AA1 71.91,83.86 v1(72.07,83.86) ; U7.AD2 73.17,86.3 v2(73.18,86.3) ; U7.B3 U7.A3 59.66,74.36 v1(59.66,74.13) ; U7.AD7 70.16,88.95 70.54,89.33 U7.AE7 v1(70.93,89.86) 71.22,90.16 71.72,90.16 ; R155.2 v1(74.21,100.51) ; v2(71,93.08) 71.34,93.42 R606.2 71.34,93.6 ; C460.2 33.36,57.31 v1(33.82,56.85) ; U7.AE5 U7.AD5 70.54,87.89 v2(70.54,87.89) ; R75.1 77.93,87.31 78,87.31 v1(78.01,87.33) 77.72,87.62 77.72,87.63 76.01,89.35 v1(75.99,89.35) 75.57,89.35 R76.1 74.95,88.73 v2(72.02,88.73) ; v1(72.8,79.38) 72.39,79.81 R174.1 ; v2(53.5,92.76) 53.5,92.73 U7.M25 U7.M24 ; v1(61.03,72.88) 60.99,72.92 U7.A1 ; U7.W2 U7.W1 71.27,82.39 v1(71.53,82.39) ; v1(74.31,86.33) 74.27,86.3 U7.AE1 ; v1(76.8,102.23) C509.2 ; U7.B6 U7.A6 57.81,75.69 v1(57.81,75.62)
  TOP w0.381: SW6.2 107.5,63.24 v1(107.5,62.71) ; M1.44 v1(121,19.37) ; M1.15 v1(106.26,13.07) ; R300.1 v1(28.16,41.78) ; M1.23 v1(112.23,10.02) ; M1.9 v1(106.27,17.27) ; v1(42.33,40.59) C500.2 v1(43.27,39.75) ; C369.2 v1(111.17,39.89) ; C553.2 v1(26.51,88.47) ; M1.48 120.74,22.17 120.81,22.24 v1(120.83,22.24) ; 15.2,93.47 C46.2 v1(14.26,93.47) ; 15.2,93.47 v1(15.2,94.6) ; 15.2,93.47 v1(15.2,92.39) ; v1(45.52,34.3) X3.4 v1(46.66,33.1) ; R698.1 v1(3.42,11.58) ; C556.1 28.11,88.44 v1(28.92,87.63) ; C540.2 v1(79.01,118.7) ; C540.2 79.83,118.5 v1(79.16,117.83) 79.77,117.22 C538.2 ; C540.2 v1(79.83,119.53) ; C538.2 79.77,116.89 v1(79.11,116.22) C539.2 ; C538.2 v1(78.96,117.09) ; U41.1 v1(92.82,59.05) ; C1.2 v1(28.47,96.72) ; C1.2 v1(26.64,95.25) ; C1.2 v1(24.66,96.72) ; v1(43.15,37.72) C250.2 43.15,36.78 v1(42.38,36.02) ; M1.20 v1(110.13,10.02) ; D35.1 v1(6.32,53.51) ; M1.7 v1(106.27,18.67) ; v1(96.07,58.88) 96.2,58.75 C578.2 ; C368.2 v1(88.61,79.12) ; v1(17.13,46.98) 17.13,46.27 C558.2 ; C220.2 v1(103.6,14.73) ; C251.2 v1(42.26,38.48) ; U41.3 v1(92.82,61.59) ; v1(119.86,24.52) M1.49 v1(120.83,23.55) ; R667.1 v1(26.51,34.67) ; v1(20.46,78.87) C41.2 v1(19.73,78.03) ; v1(23.84,76.88) C40.2 v1(22.83,77.65) ; Q5.2 v1(38.83,98.36) ; v1(120.01,1.9) J10.2 120.11,3.46 v1(120.11,4.95) ; L8.2 v1(117.74,8.26) ; L8.2 v1(117.74,6.95) ; L8.2 v1(117.11,7.64) ; R251.2 v1(47.51,5.08) ; R699.1 4.09,14 3.52,13.43 v1(3.52,13.33) ; v1(110.39,100.08) 110.58,100.27 110.58,101.94 H2.3 ; C506.2 75.13,15.9 v1(74.96,15.74) ; v1(51.19,73.49) 51.83,73.49 R70.1 ; M1.39 v1(121,15.87) ; v1(82.64,94.36) 82.18,94.83 C409.2 81.35,95.58 ; M1.45 v1(121,20.07) ; v1(42.77,30.73) 42.28,30.73 C304.2 ; C573.2 93.46,95.55 v1(93.9,95.55) ; R702.1 v1(3.55,21.62) ; R696.1 v1(120.09,73.28) ; C219.2 v1(103.6,13.59) ; v1(45.05,118.24) C395.2 v1(44.26,118.85) ; v1(117.06,1.9) J10.3 v1(117.06,4.82) ; v1(123.92,104.14) C239.2 v1(123.11,103.25) ; H2.5 111.6,100.65 v1(112.04,100.2) ; R660.1 v1(91.84,41.8) ; v1(44.67,37.72) C292.2 v1(45.64,36.78) ; v1(23.46,96.65) C2.2 v1(24.3,97.71) ; C391.2 v1(120.24,45.21) ; v1(29.06,98.41) D1.1 v1(30.19,99.57) ; R717.1 v1(87.72,112.35) ; R367.1 v1(113.73,39.47) ; J20.S3 2.93,49.67 v1(4.26,49.67) ; v1(29.81,87.88) SW9.1 v1(33.24,87.88) ; C566.2 v1(16.25,64.29) ; M1.19 v1(109.43,10.02) ; C223.2 v1(103.6,19.43) ; v1(25.37,77.15) C550.2 v1(26.11,77.88) ; C221.2 v1(103.6,15.88) ; v1(125.18,7.4) 125.14,7.45 C528.2 v1(125.9,8.25) ; C45.2 10.26,90.76 v1(10.26,91.8) ; v1(7.91,78.99) C42.2 v1(8.78,78.28) ; J20.S2 6.38,49.65 v1(6.92,50.19) ; v1(81.5,100.84) 81.08,100.42 C410.2 ; C505.2 v1(72.1,23.62) TP34.1 ; C533.2 v1(83.02,118.11) ; M1.35 v1(121,13.07) ; R668.1 v1(28.03,29.59) ; v1(43.3,29.72) 43.82,30.24 X3.2 43.36,31.37 v1(42.86,31.37) ; U37.2 88.3,93.09 v1(88.27,93.06) ; SW6.1 v1(97.96,62.74) ; C543.2 121.76,23.06 v1(121.78,23.08) ; v1(91.31,91.31) C393.2 ; C572.2 v1(107.41,102.87) ; C402.2 84.73,99.57 v1(84.8,99.57) ; C539.2 v1(79.81,114.64) ; C539.2 v1(78.88,115.52) ; R697.1 v1(3.42,8.92) ; v1(101.94,85.22) 101.54,85.22 R349.2 ; M1.61 v1(110.83,24.52) ; C283.2 v1(28.92,30.23) ; v1(124.64,23.75) 124.64,23.27 C218.2 v1(125.1,22.94) ; v1(93.07,90.03) 93.07,90.46 C401.2 ; v1(123.07,16.59) C216.2 v1(122.27,17.4) ; Q37.2 v1(23.78,92.14) ; v1(8.33,77.6) C552.2 v1(9.01,76.94) ; C501.2 8.98,46.37 v1(9.21,46.59) ; v1(14.4,39.71) 14.23,39.88 C263.2 ; U50.3 17.8,66.22 v1(18.13,66.55) ; R293.2 v1(20.92,34.8) ; SW8.2 v1(90.87,78.13) ; C305.2 v1(41.34,34.01) ; C534.2 v1(86.33,112.01) ; v1(97.6,46.53) C272.2 v1(98.4,45.8) ; C298.2 v1(47.8,6.15) ; C571.2 v1(100.83,89.13) ; C527.2 v1(122.8,10.52) ; R735.1 v1(19.52,79.76) ; M1.37 v1(121,14.47) ; v1(89.68,112.9) C557.2 v1(89.68,114.68) ; v1(79.09,112.65) C535.2 ; C367.2 v1(95.09,64.39) ; v1(7.21,40.05) 7.57,40.41 R269.2 ; C403.2 82.64,101.66 v1(82.64,101.73) ; TP31.1 5.54,30.34 6.63,30.34 v1(7.14,29.83) ; C242.2 v1(122.39,110.74) ; v1(85.39,117.3) C537.2 v1(84.55,118.11) ; C281.2 v1(72.23,15.52) ; C370.2 v1(111.3,34.93) ; R163.2 v1(122.39,111.81) ; J20.S1 v1(5.91,41.39) ; C224.2 v1(103.6,18.16) ; R8.1 v1(40,100.2) ; C217.2 122.9,23.02 122.93,23.04 v1(122.93,23.06) ; U41.2 v1(92.82,60.33) ; SW5.2 106.5,52.55 v1(104.69,52.55) ; J20.S4 v1(2.91,41.29) ; M1.59 v1(112.23,24.52) ; R37.1 v1(13.58,92.3) ; v1(106.4,11) M1.17 v1(107.41,9.98) ; R701.1 v1(3.55,19.08) ; C47.2 v1(15.99,92.46) ; v1(75.79,26.54) 75.38,26.54 C279.2 74.97,26.13 U25.2 ; SW8.1 v1(90.87,66.55) ; M1.16 v1(106.26,12.37) ; R614.1 v1(14.06,120.14) ; C44.2 v1(25.24,88.71) ; v1(3.65,92.38) Q40.2 v1(4.6,93.09) ; C392.2 v1(8.35,59.29) ; M1.54 v1(115.73,24.52) ; SW5.1 97.27,52.79 v1(97.27,53.24) ; C507.2 v1(28.92,31.37) ; C579.2 v1(118.56,59.64) ; R703.1 v1(3.55,24.16) ; R679.2 v1(89.25,41.14) ; U33.3 v1(13.5,59.5) ; SW7.2 v1(126.13,51.49) ; v1(46.07,120.4) D17.2 v1(45.2,119.53) ; M1.24 v1(112.93,10.02) ; M1.63 v1(109.43,24.63) ; C252.2 v1(48.78,5.08) ; v1(9.57,87.45) C49.2 v1(7.93,87.45) ; R666.1 v1(24.73,37.46) ; J25.5 54.98,4.82 v1(55.43,5.27) ; U31.3 122.52,47.89 122.86,48.23 R683.2 v1(123.16,48.89) ; M1.55 v1(115.03,24.52) ; R678.1 v1(88.1,41.16) ; M1.34 v1(121,12.37) ; C222.2 v1(103.6,17.02) ; R307.1 v1(25.75,29.59) ; R704.1 v1(3.55,26.7) ; R616.1 v1(8.76,105.44) ; C536.2 v1(85.57,112.6) ; v1(13.84,44.78) 13.7,44.78 C445.2 ; R308.1 v1(23.46,29.59) ; R700.1 v1(3.55,16.54) ; C576.2 v1(20.97,22.86) ; C282.2 v1(77.18,15.52) ; 81.88,111.93 81.88,111.05 U51.8 ; M1.64 v1(108.73,24.6) ; SW7.1 v1(117.13,51.49) ; C551.2 v1(20.03,77.09) ; U41.4 v1(92.82,62.87)
  TOP w0.406: 74.78,91.16 74.78,90.82 74.12,90.16 71.72,90.16 ; 74.78,91.16 v1(74.8,91.16) 77.79,91.16 79.11,89.84 v1(80.61,89.84) 80.64,89.87 81.22,89.87 83.69,87.4 83.69,86.69 v3(81.27,84.28) 80.74,83.74 79.65,83.74 78.81,84.58 78.12,84.58 77.13,85.57 77.13,86.51 R75.1 ; 74.78,91.16 73.86,91.16 73.49,91.53 R608.2 ; v1(103.19,36.65) 103.18,36.66 C270.2 ; v1(9.66,41.77) 9.19,42.24 C444.2 ; v2(49.8,117.5) 49.74,117.5 TP74.1 ; C461.2 v1(23.92,56.7) ; C446.2 1.94,38.02 v3(1.19,38.02) ; J3.2 43.93,69.91 45.04,71.02 v1(45.04,71.12) ; R449.2 81.72,92.23 v1(81.94,92.23) ; TP72.1 61,121.04 v2(61.07,121.1) ; v2(69.81,118.93) 70.32,118.42 TP71.1 ; C264.2 9.97,38.34 v1(9.97,38.15) ; C105.2 74.78,79.1 v1(75.43,79.1) 75.43,79.82 C106.2 ; R68.2 51.03,74.13 v1(51.05,74.13) ; v2(66.37,108.02) 66.37,107.52 65.78,106.93 R118.2 ; v1(83.68,94.14) 83.58,94.23 R604.2 ; v2(61.44,107.72) 61.96,108.24 TP68.1 ; v1(103.22,38.02) 103.21,38.03 C273.2 ; C268.2 v1(93.73,42.62) ; C267.2 v1(91.46,41) ; J4.3 v1(46.61,69.43) ; v1(40.54,72.74) 41.29,71.99 J3.3 ; v1(123.9,109.55) 123.91,109.57 125.16,109.57 ; J4.2 47.61,66.23 48.78,67.39 v1(48.78,67.39) ; v1(8.09,50.14) 8.09,49.61 C456.2 ; C103.2 79.35,87.64 v1(79.71,88) 80.01,88.3 C102.2 ; v1(10.22,47.24) C354.2 ; TP75.1 48.68,100.56 v2(48.91,100.33) ; v1(2.61,36.83) 2.63,36.86 2.63,36.87 C447.2
  TOP w0.508: 71.74,9.26 J19.6 ; J19.6 73.55,9.26 ; J19.6 71.74,7.45 ; J19.6 73.55,7.45 ; 41.56,18.27 J26.4 ; J26.4 43.19,18.27 ; J26.4 41.56,19.9 ; J26.4 43.19,19.9 ; 81.33,12.1 J19.5 ; J19.5 81.33,10.29 ; J19.5 83.14,12.1 ; J19.5 83.14,10.29 ; v1(21.68,97.41) C3.2 v1(20.94,98.15) ; U31.7 121,46.74 120.9,46.63 C391.2 ; v1(75.48,28.57) C570.2 v1(76.29,27.69) ; 62.6,11.43 J19.SH1 ; J19.SH1 65.91,8.11 ; J19.SH1 65.91,11.43 ; J19.SH1 62.6,8.11 ; R297.2 v1(18,8.89) ; J1.S1 22.69,122.21 ; J1.S1 20.41,127.31 ; J1.S1 20.41,122.21 ; J1.S1 22.69,127.31 ; 33.2,18.1 J27.10 ; J27.10 34.91,18.1 ; J27.10 33.2,16.38 ; J27.10 34.91,16.38 ; v1(46.91,107.52) 46.88,107.52 46.34,108.06 TP73.1 ; J1.2 28.42,124.91 ; J1.2 28.42,122.61 ; J1.2 23.67,122.61 ; J1.2 23.67,124.91 ; v1(127.65,36.62) J15.1 v1(126.19,38.5) ; C293.2 v1(40.48,36.65) ; v3(12.34,43.13) 13.33,42.14 C261.2 ; v1(4.21,110.16) C439.2 v1(3.27,111.25) ; X2.2 78.4,78.3 v1(79.09,78.99) ; J11.5 125.16,109.57 ; v1(23.54,88.56) C48.2 v1(24.27,87.76) ; v1(75.02,76.45) 75.4,76.83 75.4,77.51 X2.4 75.46,77.56 ; C294.2 v1(41.14,36.04) ; 29.41,127.31 J1.S2 ; J1.S2 29.41,122.21 ; J1.S2 31.69,122.21 ; J1.S2 31.69,127.31 ; v3(99,45.09) 98.94,45.03 C271.2 ; J27.SH1 37.19,15.04 ; J27.SH1 37.19,12.84 ; J27.SH1 34.98,15.04 ; v1(127.29,13.9) Y5.2 v1(126.04,15.33) ; C406.2 77.95,103.13 v1(78.71,103.89) ; 87.59,11.43 J19.SH2 ; J19.SH2 90.9,11.43 ; J19.SH2 90.9,8.11 ; J19.SH2 87.59,8.11 ; v3(10.38,42.44) C262.2 ; C307.2 v1(28.67,34.8) ; v1(106.85,76.89) C200.2 105.6,76.47 v1(105.16,76.47) ; C577.2 v1(52.85,125.09) ; U41.7 86.73,60.33 C408.2 v1(85.69,60.17) ; C310.2 v1(27.65,36.07) ; v1(3.09,116.28) C438.2 v1(3.09,112.19) ; R615.2 v1(8.58,101.5)
  TOP w0.762: J7.C5 v1(128.29,86.41) ; BH1.2 v1(119.98,118.75) ; BH1.2 v1(122.13,121.03) ; BH1.2 122.13,116.32 v1(121.38,115.57)
  L2_GND_1 w0.508: MH2.1 5.51,127.51 ; MH2.1 2.49,127.51 ; MH2.1 5.51,124.49 ; MH2.1 2.49,124.49 ; 71.74,7.45 J19.6 ; J19.6 71.74,9.26 ; J19.6 73.55,7.45 ; J19.6 73.55,9.26 ; 20.41,127.31 J1.S1 ; J1.S1 20.41,122.21 ; J1.S1 22.69,127.31 ; J1.S1 22.69,122.21 ; J27.10 34.75,17.94 ; J27.10 33.36,17.94 ; J27.10 34.75,16.54 ; J27.10 33.36,16.54 ; SW1.2 46.22,126.8 ; SW1.2 44.84,126.8 ; SW1.2 44.84,125.42 ; SW1.2 46.22,125.42 ; 41.56,19.9 J26.4 ; J26.4 43.19,18.27 ; J26.4 43.19,19.9 ; J26.4 41.56,18.27 ; 2.49,5.51 MH4.1 ; MH4.1 2.49,2.49 ; MH4.1 5.51,5.51 ; MH4.1 5.51,2.49 ; 29.41,122.21 J1.S2 ; J1.S2 29.41,127.31 ; J1.S2 31.69,127.31 ; J1.S2 31.69,122.21 ; J2.2 13.56,126.33 ; J2.2 13.56,127.67 ; J2.2 12.22,126.33 ; J2.2 12.22,127.67 ; 66.68,126.66 H5.6 ; H5.6 66.68,128.36 ; H5.6 68.38,128.36 ; H5.6 68.38,126.66 ; 19.49,12.84 J27.SH2 ; J27.SH2 21.7,15.04 ; J27.SH2 19.49,15.04 ; J27.SH2 21.7,12.84 ; 34.98,12.84 J27.SH1 ; J27.SH1 37.19,12.84 ; J27.SH1 34.98,15.04 ; J27.SH1 37.19,15.04 ; H1.6 80.52,124.11 ; H1.6 80.52,122.27 ; H1.6 78.67,122.27 ; H1.6 78.67,124.11 ; 62.6,11.43 J19.SH1 ; J19.SH1 65.91,8.11 ; J19.SH1 65.91,11.43 ; J19.SH1 62.6,8.11 ; 23.67,124.91 J1.2 ; J1.2 28.42,124.91 ; J1.2 28.42,122.61 ; J1.2 23.67,122.61 ; 124.49,2.49 MH3.1 ; MH3.1 127.51,5.51 ; MH3.1 127.51,2.49 ; MH3.1 124.49,5.51 ; J19.5 83.14,10.29 ; J19.5 81.33,12.1 ; J19.5 81.33,10.29 ; J19.5 83.14,12.1 ; J19.SH2 90.9,8.11 ; J19.SH2 90.9,11.43 ; J19.SH2 87.59,8.11 ; J19.SH2 87.59,11.43 ; 124.49,124.49 MH1.1 ; MH1.1 124.49,127.51 ; MH1.1 127.51,124.49 ; MH1.1 127.51,127.51
  L3_INT_1 w0.508: 33.36,16.54 J27.10 ; J27.10 33.36,17.94 ; J27.10 34.75,17.94 ; J27.10 34.75,16.54 ; 2.49,5.51 MH4.1 ; MH4.1 5.51,5.51 ; MH4.1 5.51,2.49 ; MH4.1 2.49,2.49 ; J19.SH2 90.9,11.43 ; J19.SH2 87.59,8.11 ; J19.SH2 87.59,11.43 ; J19.SH2 90.9,8.11 ; 71.74,9.26 J19.6 ; J19.6 73.55,7.45 ; J19.6 71.74,7.45 ; J19.6 73.55,9.26 ; J19.5 83.14,12.1 ; J19.5 81.33,12.1 ; J19.5 81.33,10.29 ; J19.5 83.14,10.29 ; 34.98,15.04 J27.SH1 ; J27.SH1 37.19,15.04 ; J27.SH1 34.98,12.84 ; J27.SH1 37.19,12.84 ; J27.SH2 21.7,15.04 ; J27.SH2 19.49,12.84 ; J27.SH2 21.7,12.84 ; J27.SH2 19.49,15.04 ; 41.56,19.9 J26.4 ; J26.4 43.19,19.9 ; J26.4 43.19,18.27 ; J26.4 41.56,18.27 ; 62.6,8.11 J19.SH1 ; J19.SH1 65.91,11.43 ; J19.SH1 62.6,11.43 ; J19.SH1 65.91,8.11 ; MH1.1 127.51,124.49 ; MH1.1 124.49,124.49 ; MH1.1 127.51,127.51 ; MH1.1 124.49,127.51 ; MH3.1 127.51,2.49 ; MH3.1 127.51,5.51 ; MH3.1 124.49,2.49 ; MH3.1 124.49,5.51
  L4_PWR_1 w0.508: 124.49,2.49 MH3.1 ; MH3.1 127.51,2.49 ; MH3.1 127.51,5.51 ; MH3.1 124.49,5.51
  L5_PWR_2 w0.508: MH3.1 127.51,5.51 ; MH3.1 124.49,2.49 ; MH3.1 127.51,2.49 ; MH3.1 124.49,5.51
  L6_INT_2 w0.508: J19.6 73.55,9.26 ; J19.6 71.74,9.26 ; J19.6 71.74,7.45 ; J19.6 73.55,7.45 ; H1.6 80.52,122.27 ; H1.6 78.67,122.27 ; H1.6 78.67,124.11 ; H1.6 80.52,124.11 ; MH4.1 5.51,5.51 ; MH4.1 2.49,2.49 ; MH4.1 5.51,2.49 ; MH4.1 2.49,5.51 ; 29.41,127.31 J1.S2 ; J1.S2 31.69,122.21 ; J1.S2 29.41,122.21 ; J1.S2 31.69,127.31 ; MH1.1 127.51,127.51 ; MH1.1 124.49,127.51 ; MH1.1 127.51,124.49 ; MH1.1 124.49,124.49 ; 23.67,122.61 J1.2 ; J1.2 23.67,124.91 ; J1.2 28.42,122.61 ; J1.2 28.42,124.91 ; 2.49,124.49 MH2.1 ; MH2.1 5.51,127.51 ; MH2.1 5.51,124.49 ; MH2.1 2.49,127.51 ; 66.68,128.36 H5.6 ; H5.6 68.38,126.66 ; H5.6 66.68,126.66 ; H5.6 68.38,128.36 ; J27.SH2 21.7,15.04 ; J27.SH2 21.7,12.84 ; J27.SH2 19.49,12.84 ; J27.SH2 19.49,15.04 ; J19.SH2 90.9,8.11 ; J19.SH2 90.9,11.43 ; J19.SH2 87.59,11.43 ; J19.SH2 87.59,8.11 ; 124.49,2.49 MH3.1 ; MH3.1 127.51,2.49 ; MH3.1 124.49,5.51 ; MH3.1 127.51,5.51 ; J19.5 83.14,12.1 ; J19.5 83.14,10.29 ; J19.5 81.33,12.1 ; J19.5 81.33,10.29 ; 33.36,17.94 J27.10 ; J27.10 34.75,16.54 ; J27.10 33.36,16.54 ; J27.10 34.75,17.94 ; J19.SH1 65.91,11.43 ; J19.SH1 62.6,11.43 ; J19.SH1 65.91,8.11 ; J19.SH1 62.6,8.11 ; 34.98,12.84 J27.SH1 ; J27.SH1 37.19,15.04 ; J27.SH1 37.19,12.84 ; J27.SH1 34.98,15.04 ; J26.4 43.19,19.9 ; J26.4 43.19,18.27 ; J26.4 41.56,19.9 ; J26.4 41.56,18.27 ; 12.22,127.67 J2.2 ; J2.2 13.56,126.33 ; J2.2 12.22,126.33 ; J2.2 13.56,127.67 ; 44.84,126.8 SW1.2 ; SW1.2 46.22,126.8 ; SW1.2 44.84,125.42 ; SW1.2 46.22,125.42 ; 20.41,127.31 J1.S1 ; J1.S1 22.69,127.31 ; J1.S1 22.69,122.21 ; J1.S1 20.41,122.21
  L7_GND_2 w0.508: 78.67,122.27 H1.6 ; H1.6 80.52,122.27 ; H1.6 80.52,124.11 ; H1.6 78.67,124.11 ; 2.49,124.49 MH2.1 ; MH2.1 5.51,127.51 ; MH2.1 2.49,127.51 ; MH2.1 5.51,124.49 ; MH4.1 5.51,2.49 ; MH4.1 2.49,2.49 ; MH4.1 5.51,5.51 ; MH4.1 2.49,5.51 ; 20.41,127.31 J1.S1 ; J1.S1 22.69,127.31 ; J1.S1 20.41,122.21 ; J1.S1 22.69,122.21 ; J19.SH2 90.9,11.43 ; J19.SH2 87.59,11.43 ; J19.SH2 90.9,8.11 ; J19.SH2 87.59,8.11 ; 12.22,127.67 J2.2 ; J2.2 12.22,126.33 ; J2.2 13.56,127.67 ; J2.2 13.56,126.33 ; 124.49,5.51 MH3.1 ; MH3.1 124.49,2.49 ; MH3.1 127.51,2.49 ; MH3.1 127.51,5.51 ; 81.33,12.1 J19.5 ; J19.5 83.14,12.1 ; J19.5 83.14,10.29 ; J19.5 81.33,10.29 ; 41.56,19.9 J26.4 ; J26.4 43.19,19.9 ; J26.4 41.56,18.27 ; J26.4 43.19,18.27 ; 34.98,12.84 J27.SH1 ; J27.SH1 37.19,12.84 ; J27.SH1 37.19,15.04 ; J27.SH1 34.98,15.04 ; 62.6,8.11 J19.SH1 ; J19.SH1 65.91,11.43 ; J19.SH1 65.91,8.11 ; J19.SH1 62.6,11.43 ; 44.84,126.8 SW1.2 ; SW1.2 46.22,126.8 ; SW1.2 44.84,125.42 ; SW1.2 46.22,125.42 ; J27.SH2 21.7,15.04 ; J27.SH2 19.49,12.84 ; J27.SH2 19.49,15.04 ; J27.SH2 21.7,12.84 ; J19.6 73.55,7.45 ; J19.6 73.55,9.26 ; J19.6 71.74,7.45 ; J19.6 71.74,9.26 ; 23.67,124.91 J1.2 ; J1.2 23.67,122.61 ; J1.2 28.42,124.91 ; J1.2 28.42,122.61 ; 66.68,126.66 H5.6 ; H5.6 68.38,126.66 ; H5.6 66.68,128.36 ; H5.6 68.38,128.36 ; J1.S2 31.69,127.31 ; J1.S2 29.41,127.31 ; J1.S2 31.69,122.21 ; J1.S2 29.41,122.21 ; MH1.1 127.51,124.49 ; MH1.1 127.51,127.51 ; MH1.1 124.49,124.49 ; MH1.1 124.49,127.51 ; 33.36,16.54 J27.10 ; J27.10 34.75,17.94 ; J27.10 34.75,16.54 ; J27.10 33.36,17.94
  BOTTOM w0.152: P24.1 v1(110.3,60.13)
  BOTTOM w0.178: v1(104.11,63.25) 103.85,63.5 U55.B2
  BOTTOM w0.229: v1(110.64,63.54) 110.64,63.67 P26.1 ; P10.1 41.92,8.22 41.75,8.38 41.37,8.38 ; P10.1 41.92,7.66 41.75,7.49 41.37,7.49 ; P10.1 41.24,8 ; P20.1 110.38,60.97 v1(110.74,60.61) ; P23.1 v1(110.55,45.47) ; P27.1 v1(110.3,66.6) ; P21.1 v1(110.3,62.11) ; P22.1 v1(110.55,43.06) ; P25.1 v1(110.55,48.01)
  BOTTOM w0.254: C161.2 73.51,112.42 v2(72.91,112.42) ; v2(73.79,105.94) 74.24,105.94 74.43,106.12 C162.2 ; 48.76,106.96 48.92,106.96 v2(49.17,107.22) ; C157.2 49.11,113.61 v2(49.12,113.61) ; v2(63.76,82.36) 63.54,82.14 C110.2 ; R80.1 68.48,92.74 v2(68.9,93.17) 68.6,93.47 67.68,93.47 C141.2 ; v2(68.95,86.29) 68.93,86.32 C91.2 67.86,86.32 C93.2 66.39,86.86 v2(66.36,86.84) ; C166.2 73.72,107.7 v2(73.72,107.6) ; v2(73.74,103.58) 73.97,103.36 C178.2 ; C115.2 59.32,85.24 v2(59.39,85.24) ; R81.2 65.89,112.01 65.89,112.01 v2(66.35,112.01) ; v2(65.24,93.19) 65.24,94.06 R86.1 ; C81.2 61.02,87.92 v2(61,87.9) ; R84.1 47.31,110.36 v2(47.31,109.62) ; C160.2 52.72,107.19 v2(52.72,106.72) ; C150.2 55.63,110.02 v2(54.95,110.02) ; v2(61.52,86) 61.77,86 C128.2 62.51,86.74 v2(62.79,86.74) ; C109.2 55.95,87.87 55.96,87.87 v2(56.21,88.12) ; v2(66.87,115.93) 66.87,115.93 C145.2 ; v2(56.84,115.24) 56.21,115.24 C147.2 ; C84.2 55.9,85.04 v2(56.18,85.32) ; C151.2 56.05,105.64 v2(56.71,105.64) 57.08,105.64 C176.2 ; C159.2 74.22,105.21 74.18,105.18 v2(73.73,105.18) ; C164.2 73.4,116.1 v2(72.91,115.62) ; C127.2 65.25,83.3 v2(65.25,82.57) 64.72,82.57 C118.2 ; v2(56.72,104.02) 56.78,104.07 C144.2 ; v2(57.04,112.02) 56.36,112.02 C149.2 ; C116.2 60.46,87.07 v2(60.46,87.55) ; C89.2 63.8,86.12 v2(64.18,85.74) ; v2(66.31,103.99) 66.88,103.42 C153.2 ; R82.1 47.23,112.28 v2(47.3,112.36) ; v2(56.76,83.65) 56.2,84.21 C113.2 ; v2(68.1,110.01) 68.16,110.06 C167.2 ; v2(72.15,109.98) 71.5,109.33 C165.2 70.85,108.51 v2(70.83,108.51) ; v2(59.93,85.74) 60.42,85.74 C67.2 ; C124.2 62.01,84.51 v2(61.77,84.75) ; 66.12,85.38 C99.2 66.3,85.2 v2(66.3,84.73) ; v2(61.52,88.57) 61.2,88.89 C85.2 60.29,88.52 v2(60.29,88.07) ; v2(54.1,86.3) 54.1,86.36 C92.2 ; v2(54.93,103.64) 54.72,103.43 C155.2 ; C158.2 67.48,105.24 68.12,105.89 v2(68.12,106.03) ; C163.2 72.07,106.02 v2(72.9,106.02) ; C111.2 62.52,80.95 v2(62.07,80.49) ; C98.2 65.32,84.54 v2(65.7,84.91) ; v2(65.75,114.34) 66.21,114.34 66.21,114.35 C174.2 R83.1 ; C74.2 66.89,91.06 v2(66.3,91.06) ; v2(70.06,105.75) 69.64,106.16 C168.2 ; v2(50.17,109.23) 50.1,109.23 49.59,109.74 49.59,110.54 C142.2 ; v2(50.18,105.24) 50.38,105.05 C143.2
  BOTTOM w0.305: v1(7.14,29.83) J14.27 ; v2(61.21,105.56) 61.63,105.15 R117.2 ; v1(14.39,54.1) 14.39,53.44 C266.1 ; C78.2 65.96,87.25 v2(66.36,86.84) ; C78.2 65.96,87.43 v1(65.68,87.71) 65.51,87.71 C66.2 ; C78.2 65.76,87.27 v2(65.33,86.85) ; v2(68.95,84.17) 69.43,84.65 C107.2 ; C146.2 53.27,109.9 v2(53.27,109.58) ; v2(49.18,103.97) 48.48,103.27 C172.2 ; C244.1 95.85,114.81 95.85,114.81 v1(95.66,114.81) ; C82.2 67.39,78.56 v2(67.39,78.33) ; v2(49.18,108.02) 48.42,108.02 C175.2 ; v1(105.43,103.44) 105.42,103.44 C245.2 ; C140.2 53.5,92.85 v2(53.5,92.76) ; v2(49.73,115.87) 49.8,115.8 C169.2 ; v1(107.48,109.37) U18.25 ; C243.1 95.53,111.84 v1(95.52,111.84) ; v1(105.38,105.79) 105.35,105.79 105.12,105.56 C228.2 ; U19.4 102.1,102.59 102.14,102.55 102.14,102.51 102.41,102.24 102.45,102.24 102.5,102.19 v1(102.56,102.19) ; v2(61.53,99.02) 61.18,99.37 61.18,99.72 R116.2 ; C121.2 58,75.62 v1(57.81,75.62) 57.5,75.31 R67.1 ; J14.33 9.03,32.83 9.5,33.29 v1(9.7,33.29) ; C362.2 72.88,83.75 72.18,83.75 v1(72.07,83.86) ; v1(112.03,111.1) 111.9,111.1 111.9,111.09 U17.4 ; C104.2 59.55,77.8 v2(59.4,77.8) ; C88.2 58.35,82.2 v2(58.35,82.05) 57.76,82.05 C117.2 ; v1(102.98,109.37) U18.34 ; C180.2 71.33,102.81 v2(71.33,103.64) ; C131.2 73.67,85.72 74.29,86.33 v1(74.31,86.33) ; C120.2 60.5,79.93 v2(60.47,79.93) 61.08,79.32 C108.2 ; v2(72.02,88.73) 72.44,88.31 C97.2 ; TP14.1 66.38,101.84 C156.2 66.39,102.68 v2(66.29,102.77) ; v2(57.81,90) 57.81,89.41 C112.2 ; v2(58.87,85.78) 58.37,85.78 C77.2 ; R66.1 54.38,71.31 v1(54.18,71.11) ; v2(62.79,86.74) 62.79,87.05 C100.2 63.67,87.21 v2(63.67,86.8) ; v2(65.21,76.78) 64.71,76.78 C69.2 ; R294.1 v1(112.23,114.49) ; v1(7.02,26.07) 7.02,25.76 7.45,25.33 J14.18 ; v1(105.78,116.26) 105.98,116.45 U18.9 ; v2(58.87,81.52) 59.21,81.18 59.21,80.97 ; v2(57.27,83.15) 57.11,83.15 C101.2 ; C70.2 54.97,80.46 v2(55.69,80.46) ; R35.2 68.8,80.52 v2(69.44,80.52) 69.44,81.16 C79.2 ; v2(73.18,86.3) 73.44,86.57 C130.2 ; U18.47 v1(101.31,115.13) ; v1(53.87,77.49) 53.96,77.49 R71.1 55.33,78.86 C123.2 ; C125.2 60.27,83.99 v2(59.93,83.65) ; v1(103.09,120.88) 103.09,120.88 C361.2 ; C240.2 104.49,120.91 v1(104.49,120.91) ; v1(7.3,31.83) J14.31 ; C126.2 61.03,84.75 v2(61.51,85.23) ; 48.76,106.96 C152.2 ; U18.18 v1(108.14,113.13) ; C86.2 71.53,82.67 v1(71.53,82.39) 71.47,82.34 C87.2 ; v2(70.22,91.11) 70.22,91.64 C95.2 ; C170.2 66.36,108.02 v2(66.37,108.02) ; J14.9 7.43,20.83 v1(7.23,21.03) ; v1(7.23,38.33) J14.44 ; v2(57.49,88.85) 56.98,88.34 C114.2 ; U18.45 v1(101.27,114.13) ; C177.2 v2(49.27,102.99) ; C119.2 60.57,82.16 v2(60.57,81.71) ; C68.2 63.27,74.44 v1(63.27,74.43) ; C76.2 68.62,89.14 v2(68.95,89.48)
  BOTTOM w0.381: v1(21.73,47.31) 21.57,47.47 C265.2 ; R669.2 v1(39.08,27.86) ; C287.2 36.16,32.41 ; C287.2 36.62,31.98 ; C287.2 35.7,31.98 ; v3(18.43,42.49) 18.43,43 C421.1 ; v1(109.23,56.85) 109.25,56.83 C197.2 ; R764.1 v1(9.71,80.7) ; J8.43 97.32,76 97.15,76.17 v1(97.15,76.69) ; J8.9 114.12,76.22 113.31,77.03 v1(112.92,77.03) ; C185.2 68.85,56.89 v1(68.85,57.34) 68.8,57.38 C186.2 ; v1(32.19,26.49) 31.69,26.49 C286.2 ; v1(66.87,60.81) 67.1,60.58 R691.1 ; v1(104.11,84.51) 104.11,84.12 104.12,84.1 J8.26 ; J8.35 100.52,73.68 v1(100.73,73.46) ; v1(35.48,27.57) 35.65,27.75 C302.2 ; v1(17.13,46.98) 17.07,46.98 16.68,46.58 U23.6 ; v1(36.88,26.99) 36.88,27.44 C311.2 ; R568.2 v1(114.01,97.79) ; C448.2 2.41,50.82 2.65,51.07 v1(2.65,51.07) ; C289.2 34.08,31.98 ; C289.2 33.62,32.41 ; C289.2 33.16,31.98 ; R742.1 v1(102.74,60.96) ; C423.1 C422.1 16.98,42.55 v3(16.88,42.44) ; v1(112.03,57.78) 112.06,57.81 J28.6 v1(112.06,59.83) ; v1(36.11,42.24) C308.2 v1(35.15,43.18) ; J8.34 v1(100.92,84.65) ; v1(99.97,62.7) C561.2 v1(99.97,64.39) ; R567.2 v1(112.9,97.79) ; v1(92.78,75.55) J8.S2 ; J8.S2 v1(88.96,75.55) ; J8.S2 v1(90.87,73.39) ; J8.S1 v1(118.26,75.55) ; v1(67.48,58.41) 67.48,58.28 67.02,57.82 C184.2 ; R634.1 v1(114.42,71.95) ; C420.1 19.88,43.02 19.46,42.6 v3(19.46,42.44) ; 36.61,36.58 C249.2 ; C249.2 37.23,36.02 ; C249.2 37.85,36.58 ; v1(94.33,84.62) 94.52,84.43 J8.50 ; C544.2 v1(24.35,39.29) ; J8.15 v1(111.72,73.45) ; C295.2 32.96,34.94 ; C295.2 32.96,35.76 ; C295.2 33.39,35.31 ; 32.96,34.94 32.96,34.85 ; 32.96,34.94 32.81,34.79 v1(32.81,34.3) ; C297.2 34.13,36.58 ; C297.2 33.57,35.95 ; C297.2 33.57,37.33 ; v1(106.21,62.67) 106.2,62.66 C559.2 v1(104.54,62.66) ; C542.2 7.9,80.31 v1(7.34,79.75) ; 35.83,36.76 C296.2 ; C296.2 36.29,37.19 ; C296.2 35.37,37.19 ; v1(113,50.65) 112.19,51.46 J28.3 112.11,51.51 v1(112.11,52.45) ; J8.37 v1(99.72,76.6) ; R635.1 v1(111.43,71.75) ; R40.1 16.14,92.6 v1(15.99,92.46) ; v1(42.48,37.76) 42.07,37.36 R741.2 ; C288.2 35.35,31.98 ; C288.2 34.43,31.98 ; C288.2 34.89,32.41 ; v1(103.98,64.73) 103.98,64.77 104.18,64.97 C560.2 v1(104.18,66.42) ; J8.21 v1(106.12,73.45) ; C187.2 73.48,61.02 72.94,61.02 v1(72.88,61.08) ; C567.2 22.19,66.42 23.09,67.32 v1(23.09,67.38) ; v1(103.09,73.15) 103.09,73.79 102.92,73.96 J8.29 ; C508.2 42.23,30.73 v1(42.77,30.73) 43.6,30.73 C280.2 43.88,30.3 v1(43.3,29.72) 42.59,29.72 C284.2 ; C503.2 v1(116.4,86.11) ; J8.40 v1(98.52,84.65) ; Q7.2 v1(95.28,57.98) ; C291.2 v1(32.99,26.87) ; 31.48,32.33 C290.2 ; C290.2 32.72,32.33 ; C290.2 32.1,32.89 ; U52.3 19.98,66.22 v1(19.65,66.55) ; C303.2 v1(33.49,39.5) ; v1(104.15,76.55) 104.1,76.55 103.72,76.16 J8.27 ; Q8.2 v1(106.04,50.2) ; J8.18 v1(107.32,84.65) ; R131.1 v1(29.08,34.16)
  BOTTOM w0.406: R254.1 60.66,23.48 v1(60.66,24.2) ; v1(46.46,26.5) 46.46,25.77 R250.2 ; v1(97.74,110.77) C227.2 ; v1(55.86,24.08) 55.86,23.36 R126.1 ; v1(112.23,108.97) 112.02,108.75 C241.2 ; v1(70.93,89.86) 70.93,89.19 C94.2 ; C366.2 51.27,95.24 v2(50.89,94.85) ; Y4.2 6.35,45.41 v1(7.09,45.41) ; v1(45.49,26.49) 45.18,26.18 C301.2
  BOTTOM w0.508: 1.61,6.39 MH4.1 ; MH4.1 1.61,1.61 ; MH4.1 6.39,6.39 ; MH4.1 6.39,1.61 ; 43.53,5.08 42.87,5.74 C300.1 41.9,5.74 41.75,5.59 ; 34.98,12.84 J27.SH1 ; J27.SH1 37.19,15.04 ; J27.SH1 34.98,15.04 ; J27.SH1 37.19,12.84 ; U30.6 58.39,12.52 C525.2 v1(58.59,11.35) ; v1(128.37,68.09) J28.S3 v1(128.37,65.88) ; v1(73.06,55.64) 73.06,55.82 C182.2 ; v1(77.59,81.31) 77.44,81.45 C96.2 ; v1(113.86,65.88) J28.S1 v1(113.86,68.33) ; 20.41,122.21 J1.S1 ; J1.S1 22.69,122.21 ; J1.S1 22.69,127.31 ; J1.S1 20.41,127.31 ; 13.56,126.33 J2.2 13.56,127.67 ; 29.41,127.31 J1.S2 ; J1.S2 31.69,127.31 ; J1.S2 29.41,122.21 ; J1.S2 31.69,122.21 ; J19.5 83.14,12.1 ; J19.5 83.14,10.29 ; J19.5 81.33,10.29 ; J19.5 81.33,12.1 ; C181.2 72.83,58.72 v1(72.88,58.67) ; X5.4 91.41,116.56 v1(90.26,116.56) ; J27.10 34.91,18.1 ; J27.10 34.91,16.38 ; J27.10 33.2,16.38 ; J27.10 33.2,18.1 ; C195.2 109.6,52.1 v1(109.66,52.16) ; v1(95.19,110.26) X5.2 v1(93.95,108.8) ; J19.SH2 90.9,8.11 ; J19.SH2 87.59,11.43 ; J19.SH2 87.59,8.11 ; J19.SH2 90.9,11.43 ; v3(83.74,83.14) 83.42,82.82 C129.2 ; C306.2 42,38.23 v1(42.26,38.48) ; J28.3 v1(110.95,51.46) ; v1(129.11,38.35) 128.37,39.09 J28.S4 v1(128.37,41.02) ; v1(113.38,43.31) 113.38,42.37 J28.S2 v1(113.86,40.77) ; v1(47.06,103.78) C190.2 46.91,105.05 C189.2 v1(46.91,107.52) ; v1(96.54,39.01) 97.37,38.18 C269.2 ; U11.4 v3(42.33,96.64) ; J1.2 28.42,122.61 ; J1.2 23.67,122.61 ; J1.2 28.42,124.91 ; J1.2 23.67,124.91 ; 71.74,9.26 J19.6 ; J19.6 73.55,9.26 ; J19.6 73.55,7.45 ; J19.6 71.74,7.45 ; 19.49,12.84 J27.SH2 ; J27.SH2 21.7,15.04 ; J27.SH2 21.7,12.84 ; J27.SH2 19.49,15.04 ; J8.4 v1(116.12,84.6) ; MH2.1 6.39,128.39 ; MH2.1 6.39,123.61 ; MH2.1 1.61,123.61 ; v1(54.26,14.52) Q25.2 ; C285.2 29.63,31.37 v1(28.92,31.37) ; C226.2 v1(100.89,120.85) ; C183.2 v1(72.55,54.04) ; C309.2 42.33,40.01 v1(42.33,40.59) ; 65.91,8.11 J19.SH1 65.91,11.43 ; R303.2 v1(38.32,8.76) ; C504.2 v1(92.73,84.96) ; v3(81.27,84.28) 81.08,84.47 C90.2 ; v1(65.37,55.5) 66.13,56.26 C188.2 ; C569.2 v1(12.03,122.43) ; v1(97.12,73.15) 97.15,73.13 C201.2 ; C196.2 v1(110.3,52.29)
  vias: v1(3.24,53.38) v1(3.27,51.44) v1(4.17,56.01) v1(4.16,52.45) v1(4.94,55.14) v1(6.57,31.28) v1(6.7,34.44) v1(6.69,29.12) v1(6.77,51.36) v1(7.03,52.02) v1(14.83,87.64) v1(14.85,86.11) v1(14.93,48.74) v1(15.72,88.48) v1(15.7,87.64) v1(15.75,86.12) v1(15.72,85.25) v1(17.23,88.47) v1(17.21,87.61) v1(17.25,86.12) v1(17.25,85.24) v1(17.75,71.25) v1(18.06,87.67) v1(18.1,86.07) v1(18.89,67.31) v1(18.89,66.55) v1(18.89,65.79) v1(19.46,25.05) v1(19.74,29.3) v1(20.08,23.56) v1(20,21.24) v1(20.66,17.21) v1(21.5,29.38) v1(21.86,28.4) v1(22.19,24.56) v1(23.13,28.39) v1(23.97,60.33) v1(24.8,28.35) v1(24.98,26.27) v1(25.11,61.34) v1(25.14,14.41) v1(26.44,28.36) v1(26.76,45.97) v1(26.76,45.09) v1(27.14,76.83) v1(27.91,45.97) v1(27.91,45.09) v1(28.41,42.29) v1(29.18,46.48) v1(29.33,14.41) v1(30.45,73.91) v1(30.45,72.14) v1(30.7,78.36) v1(32.22,70.61) v1(32.35,61.85) v1(32.35,60.07) v1(32.84,33.33) v1(33.88,34.54) v1(34.22,37.3) v1(34.38,77.85) v1(34.76,34.54) v1(34.89,73.03) v1(34.83,37.17) v1(34.84,21.8) v1(35.53,35.94) v1(35.53,35.31) v1(35.53,34.54) v1(35.53,33.78) v1(35.53,32.89) v1(36.29,34.54) v1(36.92,61.59) v1(37.05,34.54) v1(38.14,36.39) v1(38.15,35.62) v1(38.14,34.75) v1(38.15,33.71) v1(38.1,32.5) v1(39.08,26.61) v1(40.53,7.8) v1(40.53,6.66) v1(40.53,5.54) v1(40.53,4.41) v1(40.53,3.28) v1(42.78,4.41) v1(42.78,3.28) v1(43.58,26.3) v1(44.61,39.63) v1(46.73,39.7) v1(46.77,36.97) v1(47.49,30.78) v1(50.85,91.45) v1(58.26,45.21) v1(58.26,43.18) v1(58.26,41.02) v1(58.39,47.37) v1(58.64,34.67) v1(59.15,37.08) v1(59.66,36.07) v1(60.16,37.08) v1(60.42,47.37) v1(60.42,45.21) v1(60.42,43.18) v1(60.42,41.02) v1(60.67,34.67) v1(60.67,32.51) v1(62.45,45.21) v1(62.45,43.18) v1(62.45,41.02) v1(62.7,37.08) v1(64.61,43.18) v1(64.61,41.02) v1(64.61,34.54) v1(65.12,15.24) v1(65.5,35.81) v1(65.63,49.4) v1(65.63,37.08) v1(66.26,23.5) v1(66.77,47.37) v1(66.77,36.58) v1(66.77,34.54) v1(67.91,52.96) v1(68.8,34.54) v1(69.31,19.43) v1(69.31,15.24) v1(71.72,52.07) v1(72.36,124.97) v1(72.36,122.68) v1(72.36,120.27) v1(72.36,42.29) v1(73.56,94.62) v1(73.75,23.5) v1(73.83,96.29) v1(74.01,40.51) v1(74.52,46.23) v1(74.64,23.5) v1(74.72,119.88) v1(75.53,23.5) v1(75.66,120.48) v1(75.66,119.89) v1(75.65,119.3) v1(76.52,119.87) v1(77.94,46.48) v1(77.94,42.93) v1(78.45,114.17) v1(79.27,113.26) v1(79.46,97.5) v1(79.98,98.04) v1(79.98,96.9) v1(81.75,106.73) v1(82.52,47.62) v1(82.52,43.43) v1(82.52,41.27) v1(83.03,128.48) v1(84.07,52.14) v1(84.22,53.27) v1(84.3,128.48) v1(84.44,68.35) v1(84.7,55.97) v1(85.57,128.48) v1(86.84,128.48) v1(87.1,55.86) v1(87.25,53.27) v1(87.47,28.19) v1(88.11,128.48) v1(88.73,64.84) v1(88.99,98.81) v1(89.38,128.48) v1(89.88,27.18) v1(89.95,55.78) v1(90.95,53.2) v1(91.23,80.52) v1(91.66,28.19) v1(91.99,106.53) v1(93.57,98.55) v1(94.07,27.18) v1(95.24,39.01) v1(96.52,40.26) v1(96.52,37.72) v1(97.8,39.04) v1(98.35,25.03) v1(98.35,24.13) v1(98.35,23.23) v1(98.35,22.33) v1(98.35,21.43) v1(98.35,20.53) v1(98.35,19.63) v1(98.35,18.73) v1(98.35,17.84) v1(98.35,16.94) v1(98.35,16.04) v1(98.35,15.14) v1(98.35,14.24) v1(98.35,13.34) v1(98.35,12.57) v1(98.35,11.54) v1(98.35,10.64) v1(98.35,9.74) v1(98.35,8.84) v1(98.35,7.94) v1(98.35,7.05) v1(98.35,6.15) v1(98.35,5.25) v1(98.35,4.35) v1(98.35,3.45) v1(98.35,2.55) v1(98.35,1.65) v1(98.36,0.99) v1(99.25,25.03) v1(99.26,0.99) v1(99.79,73.28) v1(100.15,25.03) v1(100.16,0.99) v1(101.05,25.03) v1(101.95,25.03) v1(102.46,73.41) v1(102.85,25.03) v1(103.75,25.03) v1(103.85,73.41) v1(104.23,111.25) v1(104.36,113.54) v1(104.64,25.03) v1(105.54,28.63) v1(105.54,27.73) v1(105.54,26.83) v1(105.54,25.93) v1(105.54,25.06) v1(106.44,28.63) v1(107.09,9.06) v1(107.09,8.14) v1(107.09,7.22) v1(107.09,6.3) v1(107.09,5.38) v1(107.09,4.46) v1(107.09,3.54) v1(107.09,2.62) v1(107.09,1.67) v1(107.34,28.63) v1(107.35,0.97) v1(107.79,8.56) v1(107.79,7.64) v1(107.79,6.72) v1(107.79,5.8) v1(107.79,4.88) v1(107.79,3.96) v1(107.79,3.05) v1(107.79,2.13) v1(108.24,28.63) v1(108.25,0.97) v1(108.37,21.84) v1(108.37,19.07) v1(108.38,15.5) v1(108.39,14.14) v1(108.45,20.43) v1(108.4,17.32) v1(108.4,12.6) v1(108.49,9.06) v1(108.49,8.14) v1(108.49,7.22) v1(108.49,6.3) v1(108.49,5.38) v1(108.49,4.46) v1(108.49,3.54) v1(108.49,2.62) v1(108.49,1.67) v1(108.9,21.07) v1(108.9,19.67) v1(108.9,18.27) v1(108.9,16.17) v1(108.9,14.77) v1(108.9,13.37) v1(108.95,12.04) v1(109.14,28.63) v1(109.14,22.62) v1(109.15,0.97) v1(109.22,8.58) v1(109.22,7.66) v1(109.22,6.74) v1(109.22,5.82) v1(109.22,4.9) v1(109.22,3.98) v1(109.22,3.06) v1(109.22,2.14) v1(109.78,21.12) v1(109.78,19.72) v1(109.78,18.32) v1(109.78,16.22) v1(109.78,14.82) v1(109.78,13.42) v1(109.83,73.51) v1(109.83,22.01) v1(109.83,17.22) v1(109.83,12.44) v1(109.89,9.06) v1(109.89,8.14) v1(109.89,7.22) v1(109.89,6.3) v1(109.89,5.38) v1(109.89,4.46) v1(109.89,3.54) v1(109.89,2.62) v1(109.89,1.67) v1(110.04,28.63) v1(110.05,0.97) v1(110.49,22.44) v1(110.48,20.43) v1(110.49,19.03) v1(110.48,15.53) v1(110.49,14.13) v1(110.44,11.98) v1(110.66,8.6) v1(110.66,7.68) v1(110.66,6.76) v1(110.66,5.84) v1(110.66,4.92) v1(110.66,4) v1(110.66,3.08) v1(110.66,2.16) v1(110.94,28.63) v1(110.95,0.97) v1(111.18,21.12) v1(111.18,19.72) v1(111.18,18.32) v1(111.18,16.22) v1(111.18,14.82) v1(111.18,13.42) v1(111.23,22.01) v1(111.23,17.22) v1(111.23,12.44) v1(111.41,9.09) v1(111.41,8.17) v1(111.41,7.25) v1(111.41,6.33) v1(111.41,5.41) v1(111.41,4.49) v1(111.41,3.57) v1(111.41,2.65) v1(111.41,1.7) v1(111.84,28.63) v1(111.86,20.43) v1(111.87,19.03) v1(111.86,15.53) v1(111.87,14.13) v1(111.87,11.98) v1(111.85,0.97) v1(111.92,22.42) v1(112.17,76.48) v1(112.11,8.59) v1(112.11,7.67) v1(112.11,6.75) v1(112.11,5.83) v1(112.11,4.91) v1(112.11,3.99) v1(112.11,3.07) v1(112.11,2.15) v1(112.58,21.12) v1(112.58,19.72) v1(112.58,18.32) v1(112.58,16.22) v1(112.58,14.82) v1(112.58,13.42) v1(112.63,22.01) v1(112.63,17.35) v1(112.63,12.44) v1(112.74,119.25) v1(112.74,28.63) v1(112.75,0.97) v1(112.81,9.09) v1(112.81,8.17) v1(112.81,7.25) v1(112.81,6.33) v1(112.81,5.41) v1(112.81,4.49) v1(112.81,3.57) v1(112.81,2.65) v1(112.81,1.7) v1(113.53,8.61) v1(113.53,7.69) v1(113.53,6.77) v1(113.53,5.85) v1(113.53,4.93) v1(113.53,4.01) v1(113.53,3.09) v1(113.53,2.17) v1(113.64,28.63) v1(113.65,22.44) v1(113.68,21.07) v1(113.68,19.67) v1(113.68,18.27) v1(113.68,16.17) v1(113.68,14.77) v1(113.68,13.37) v1(113.67,12.02) v1(113.65,0.97) v1(113.76,73.53) v1(114.21,9.09) v1(114.21,8.17) v1(114.21,7.25) v1(114.21,6.33) v1(114.21,5.41) v1(114.21,4.49) v1(114.21,3.57) v1(114.21,2.65) v1(114.21,1.7) v1(114.53,28.63) v1(114.54,0.97) v1(114.68,21.12) v1(114.68,19.72) v1(114.68,18.32) v1(114.68,16.22) v1(114.68,14.82) v1(114.68,13.42) v1(114.73,22.01) v1(114.73,17.22) v1(114.73,12.44) v1(114.98,8.63) v1(114.98,7.71) v1(114.98,6.79) v1(114.98,5.87) v1(114.98,4.95) v1(114.98,4.03) v1(114.98,3.11) v1(114.98,2.19) v1(115.16,73.53) v1(115.38,20.43) v1(115.39,19.03) v1(115.38,15.53) v1(115.39,14.13) v1(115.43,28.63) v1(115.44,22.44) v1(115.43,11.94) v1(115.44,0.97) v1(115.73,9.85) v1(115.79,8.89) v1(115.79,8.25) v1(115.79,7.65) v1(115.79,7.06) v1(115.79,6.48) v1(115.79,5.92) v1(115.79,5.33) v1(115.79,4.72) v1(115.79,4.14) v1(115.79,3.56) v1(115.79,2.93) v1(115.79,2.29) v1(116.08,21.12) v1(116.08,19.72) v1(116.08,18.32) v1(116.08,16.22) v1(116.08,14.82) v1(116.08,13.42) v1(116.13,22.01) v1(116.13,17.22) v1(116.13,12.44) v1(116.2,1.67) v1(116.33,28.63) v1(116.34,0.97) v1(116.43,9.85) v1(116.46,9.16) v1(116.47,8.49) v1(116.48,7.69) v1(116.5,6.4) v1(116.5,5.74) v1(116.51,7.01) v1(116.52,5.15) v1(116.68,119.38) v1(116.76,20.43) v1(116.77,19.03) v1(116.76,15.53) v1(116.77,14.13) v1(116.85,22.47) v1(116.86,11.96) v1(117.13,9.85) v1(117.15,9.06) v1(117.16,8.33) v1(117.19,6.75) v1(117.17,5.39) v1(117.23,28.63) v1(117.21,6.01) v1(117.24,0.97) v1(117.48,21.12) v1(117.48,19.72) v1(117.48,18.32) v1(117.48,16.22) v1(117.48,14.82) v1(117.48,13.42) v1(117.53,22.01) v1(117.53,17.22) v1(117.53,12.44) v1(117.63,4.93) v1(117.74,9.07) v1(117.73,6.33) v1(117.74,5.65) v1(117.77,1.89) v1(117.83,9.85) v1(118.13,28.63) v1(118.14,0.97) v1(118.24,22.58) v1(118.33,114.3) v1(118.31,11.97) v1(118.47,21.07) v1(118.47,19.67) v1(118.47,18.27) v1(118.47,16.17) v1(118.47,14.77) v1(118.47,13.37) v1(118.53,1.89) v1(118.7,20.38) v1(118.73,22.03) v1(118.88,18.98) v1(118.86,17.22) v1(118.86,15.5) v1(118.86,14) v1(118.88,12.81) v1(119.03,28.63) v1(119.04,0.97) v1(119.24,1.89) v1(119.38,8.59) v1(119.38,7.84) v1(119.36,7.11) v1(119.37,6.39) v1(119.36,5.64) v1(119.4,9.31) v1(119.44,4.96) v1(119.73,80.56) v1(119.86,9.68) v1(119.93,28.63) v1(119.94,0.97) v1(120.11,70.1) v1(120.11,68.54) v1(120.11,8.64) v1(120.11,7.87) v1(120.11,7.11) v1(120.11,6.48) v1(120.11,5.71) v1(120.36,9.27) v1(120.79,10.2) v1(120.83,28.63) v1(120.87,8.9) v1(120.86,8.31) v1(120.87,7.73) v1(120.87,7.11) v1(120.87,6.48) v1(120.87,5.84) v1(120.87,5.21) v1(120.87,1.65) v1(120.84,0.97) v1(121,4.45) v1(121,3.81) v1(121,3.18) v1(121,2.41) v1(121.38,92.02) v1(121.38,67.45) v1(121.63,94.27) v1(121.78,65.67) v1(121.73,28.63) v1(122.01,60.58) v1(122.23,66.23) v1(122.23,65.14) v1(122.65,99.82) v1(122.63,28.63) v1(123.16,90.68) v1(123.16,63.63) v1(123.16,61.85) v1(123.16,60.58) v1(123.53,28.63) v1(124.43,28.63) v1(125.32,28.63) v1(125.82,103) v1(125.82,99.82) v1(125.82,96.65) v1(126.22,28.63) v1(126.45,76.02) v1(127.03,74.37) v1(127.12,28.63) v1(128.02,28.63) v1(128.29,75.9) v1(128.36,73.19) v1(128.56,27.73) v1(128.56,26.83) v1(128.56,25.93) v1(128.56,25.03) v1(128.56,24.13) v1(128.61,28.61) v2(41.95,75.66) v2(41.95,74.54) v2(42.5,99.6) v2(43.18,76.91) v2(43.16,75.64) v2(43.19,74.52) v2(43.25,73.37) v2(43.36,99.57) v2(44.23,100.92) v2(44.22,100.14) v2(44.22,99.6) v2(44.21,98.92) v2(44.22,98.33) v2(45.11,99.57) v2(46.08,99.58) v2(49.14,98.02) v2(49.9,95.58) v2(50.95,113.23) v2(51.21,118.91) v2(51.7,97.63) v2(52.49,108.71) v2(52.94,98.2) v2(53,96.35) v2(53.01,120.64) v2(53.34,105.4) v2(54.97,120.66) v2(56.81,120.66) v2(57.78,118) v2(58.88,121.1) v2(58.82,116.28) v2(60.9,113.95) v2(61.16,103.96) v2(61.21,119.35) v2(61.74,92.08) v2(62.14,112.06) v2(62.38,110.39) v2(62.48,90.91) v2(62.65,120.18) v2(63.11,115.65) v2(63.2,108.55) v2(63.12,91.08) v2(63.57,114.09) v2(63.64,121.1) v2(63.7,91.54) v2(64.18,91.08) v2(65.84,121.1) v2(65.93,119.94) v2(67.9,119.51) v2(68.32,95.14) v2(69.08,109.04) v2(69.5,96.32) v2(70.3,94.41) v2(71.09,117.61) v2(72.1,110.79) v2(73.87,110.87) v2(74.43,112.63) v2(74.97,107.69) v2(107.33,119.82) v2(107.32,118.47) v3(1.24,121.92) v3(1.26,120.22) v3(1.26,117.68) v3(1.26,115.14) v3(1.26,112.6) v3(1.26,110.06) v3(1.26,79.58) v3(1.26,74.5) v3(1.26,71.96) v3(1.24,65.41) v3(1.26,61.8) v3(1.26,36.4) v3(1.36,55.88) v3(1.76,8.13) v3(1.9,28.79) v3(2.13,92.7) v3(2.57,107.94) v3(2.57,104.39) v3(2.57,100.84) v3(3.46,99.07) v3(3.46,95.52) v3(3.59,28.79) v3(4.02,73.26) v3(6.06,122.15) v3(6.08,118.64) v3(6.93,1.42) v3(9.47,1.42) v3(9.72,54.95) v3(9.93,14.04) v3(9.96,9.53) v3(10.78,6.24) v3(12.01,1.42) v3(13.3,3.84) v3(13.76,45.72) v3(14.57,122.55) v3(14.55,1.42) v3(14.7,126.62) v3(15.11,62.58) v3(15.38,128.5) v3(15.46,124.33) v3(16.73,126.62) v3(16.73,122.55) v3(17.09,1.42) v3(17.76,119.68) v3(17.92,128.5) v3(18,124.33) v3(18.25,3.8) v3(19.02,126.62) v3(19.14,122.55) v3(19.63,1.42) v3(20.46,128.5) v3(22.17,1.42) v3(23,128.5) v3(23.33,122.3) v3(23.41,3.71) v3(24.35,126.75) v3(24.71,1.42) v3(25.54,128.5) v3(27.25,1.42) v3(28.08,128.5) v3(28.16,126.75) v3(28.47,3.77) v3(28.8,122.3) v3(29.79,1.42) v3(30.62,128.5) v3(32.22,126.75) v3(32.35,122.43) v3(32.33,1.42) v3(33.16,128.5) v3(33.37,124.33) v3(33.66,3.79) v3(34.38,126.75) v3(34.51,122.43) v3(34.87,1.42) v3(35.7,128.5) v3(35.78,124.33) v3(36.92,126.75) v3(36.92,122.43) v3(37.41,1.42) v3(38.24,128.5) v3(38.45,124.33) v3(38.67,3.77) v3(39.06,21.69) v3(39.34,126.75) v3(39.46,122.43) v3(39.95,1.42) v3(40.78,128.5) v3(42.49,1.42) v3(43.32,128.5) v3(45.03,1.42) v3(45.86,128.5) v3(47.54,21.62) v3(47.57,1.42) v3(48.4,128.5) v3(50.13,18.33) v3(50.94,128.5) v3(53.48,128.5) v3(56.23,128.52) v3(58.56,128.5) v3(59.78,4.04) v3(61.1,128.5) v3(62.81,1.42) v3(63.64,128.5) v3(64.71,20.11) v3(65.25,5.63) v3(65.35,1.42) v3(66.18,128.5) v3(67.89,1.42) v3(68.72,128.5) v3(68.71,17.7) v3(68.74,11.86) v3(68.8,5.63) v3(70.43,1.42) v3(71.26,128.5) v3(72.35,5.63) v3(72.97,1.42) v3(73.8,128.5) v3(75.51,1.42) v3(75.89,5.63) v3(76.34,128.5) v3(78.05,1.42) v3(78.88,128.5) v3(79.35,14.71) v3(79.44,5.63) v3(79.81,20.49) v3(80.59,1.42) v3(81.42,128.5) v3(82.9,14.71) v3(82.99,5.63) v3(83.13,1.42) v3(85.67,1.42) v3(86.54,5.63) v3(88.16,1.42) v3(89.83,105.92) v3(90.09,5.63) v3(90.7,1.42) v3(93.88,1.39) v3(113.99,58.34) v3(114.16,53.66) v3(118.79,106.15) v3(128.25,47.15) v3(128.41,54.96) v3(128.53,61.4) v3(128.64,71.27) v3(128.64,63.65)
